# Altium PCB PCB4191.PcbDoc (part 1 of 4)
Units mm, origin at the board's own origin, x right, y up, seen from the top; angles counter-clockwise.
Board outline 160 x 160 mm, 6 copper layers (Top Layer, IM1 RIS, IM2 Signal, IM3 Signal, IM4 GND, Bottom Layer), stack 1.582 mm thick; 143 components, 121 nets, 430 pads, 4983 vias.
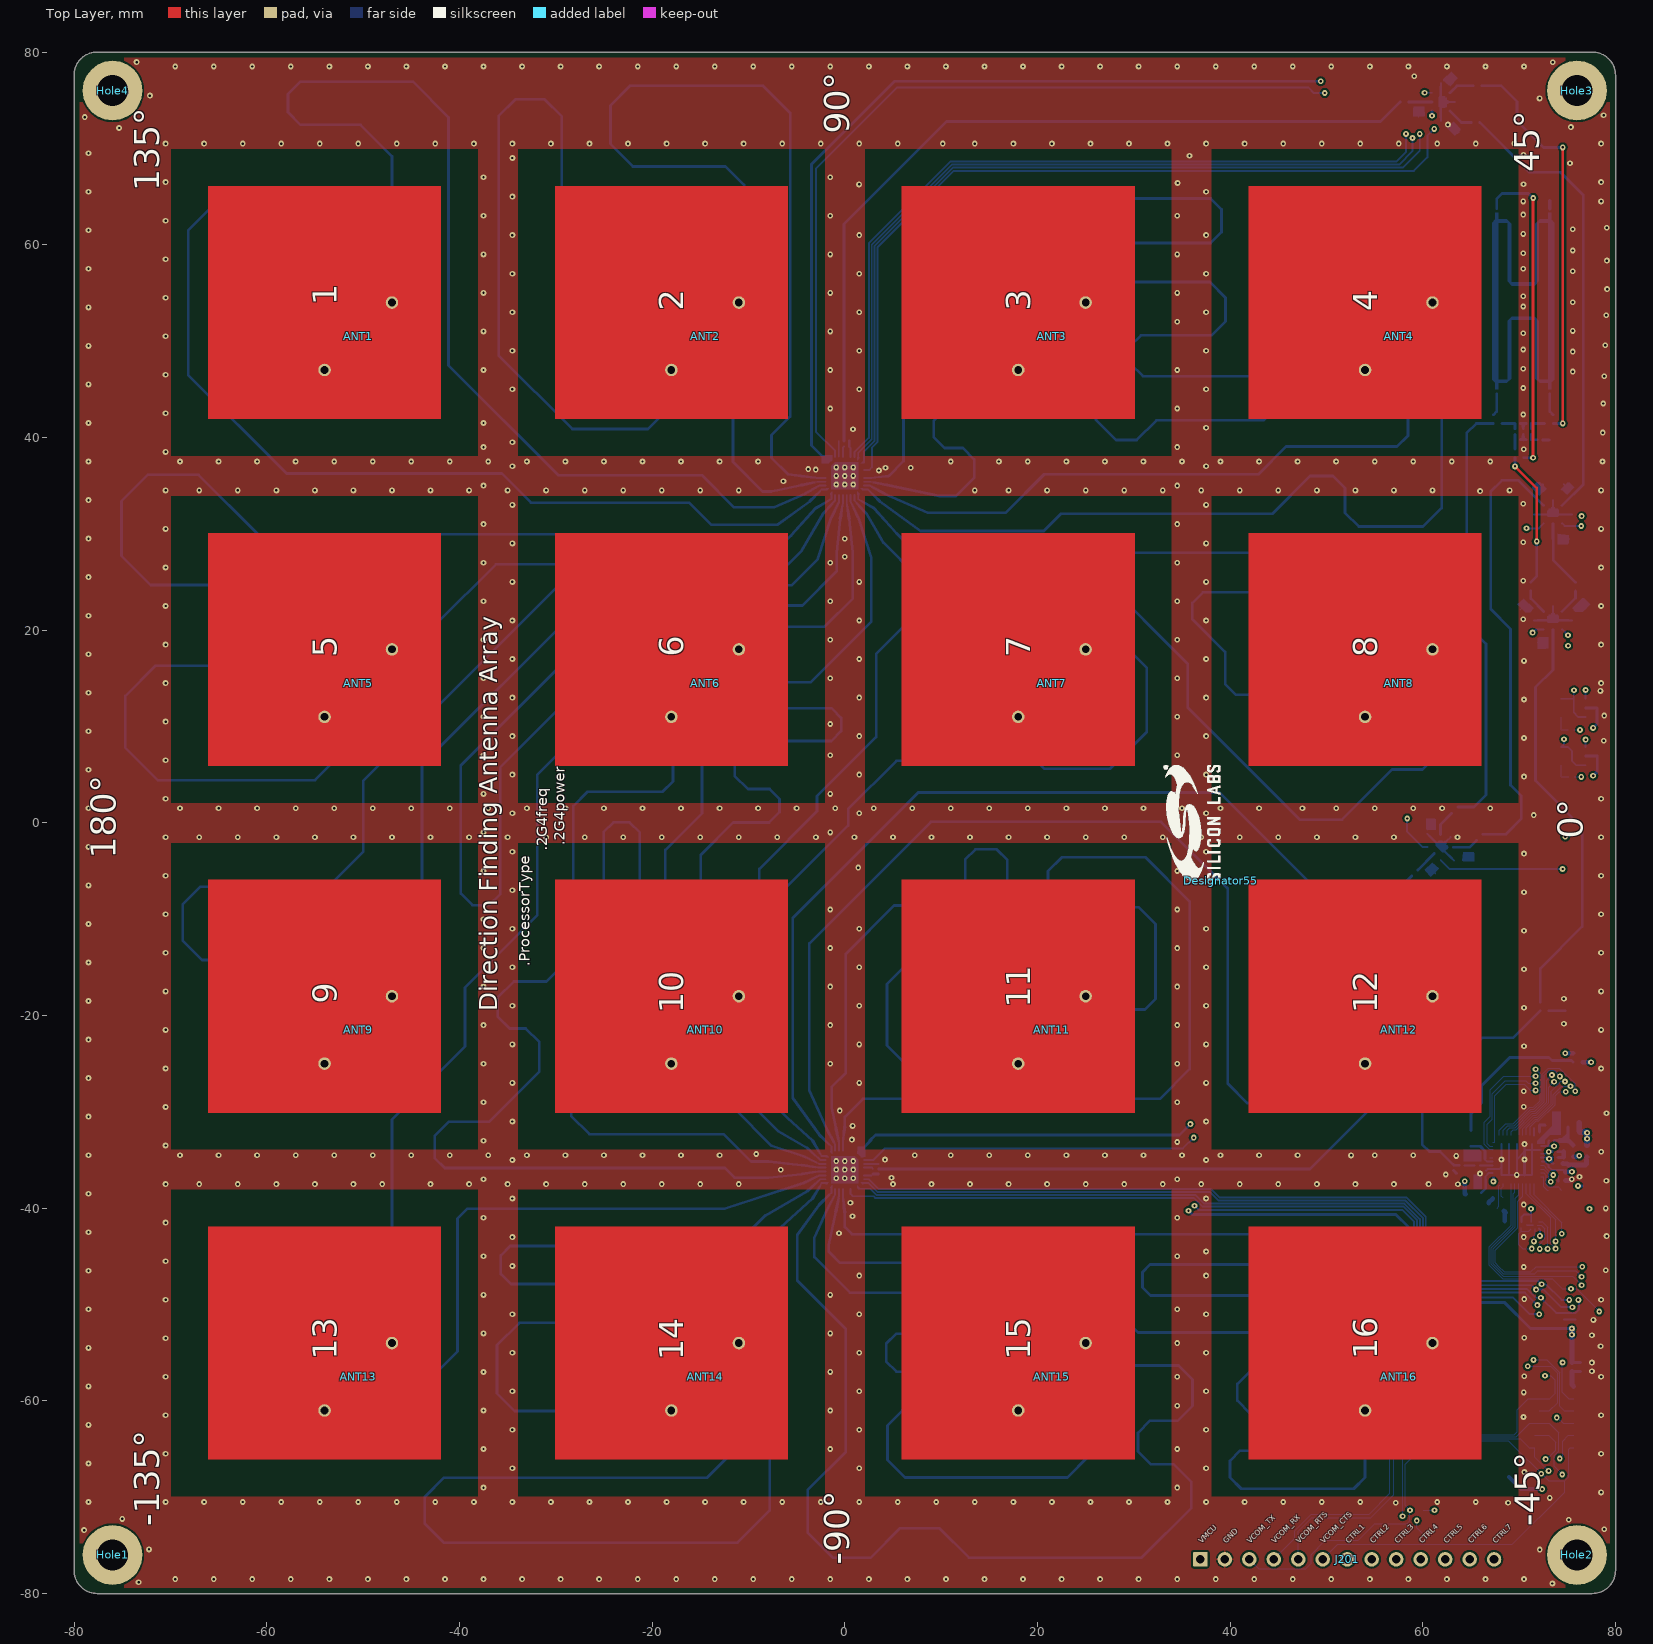
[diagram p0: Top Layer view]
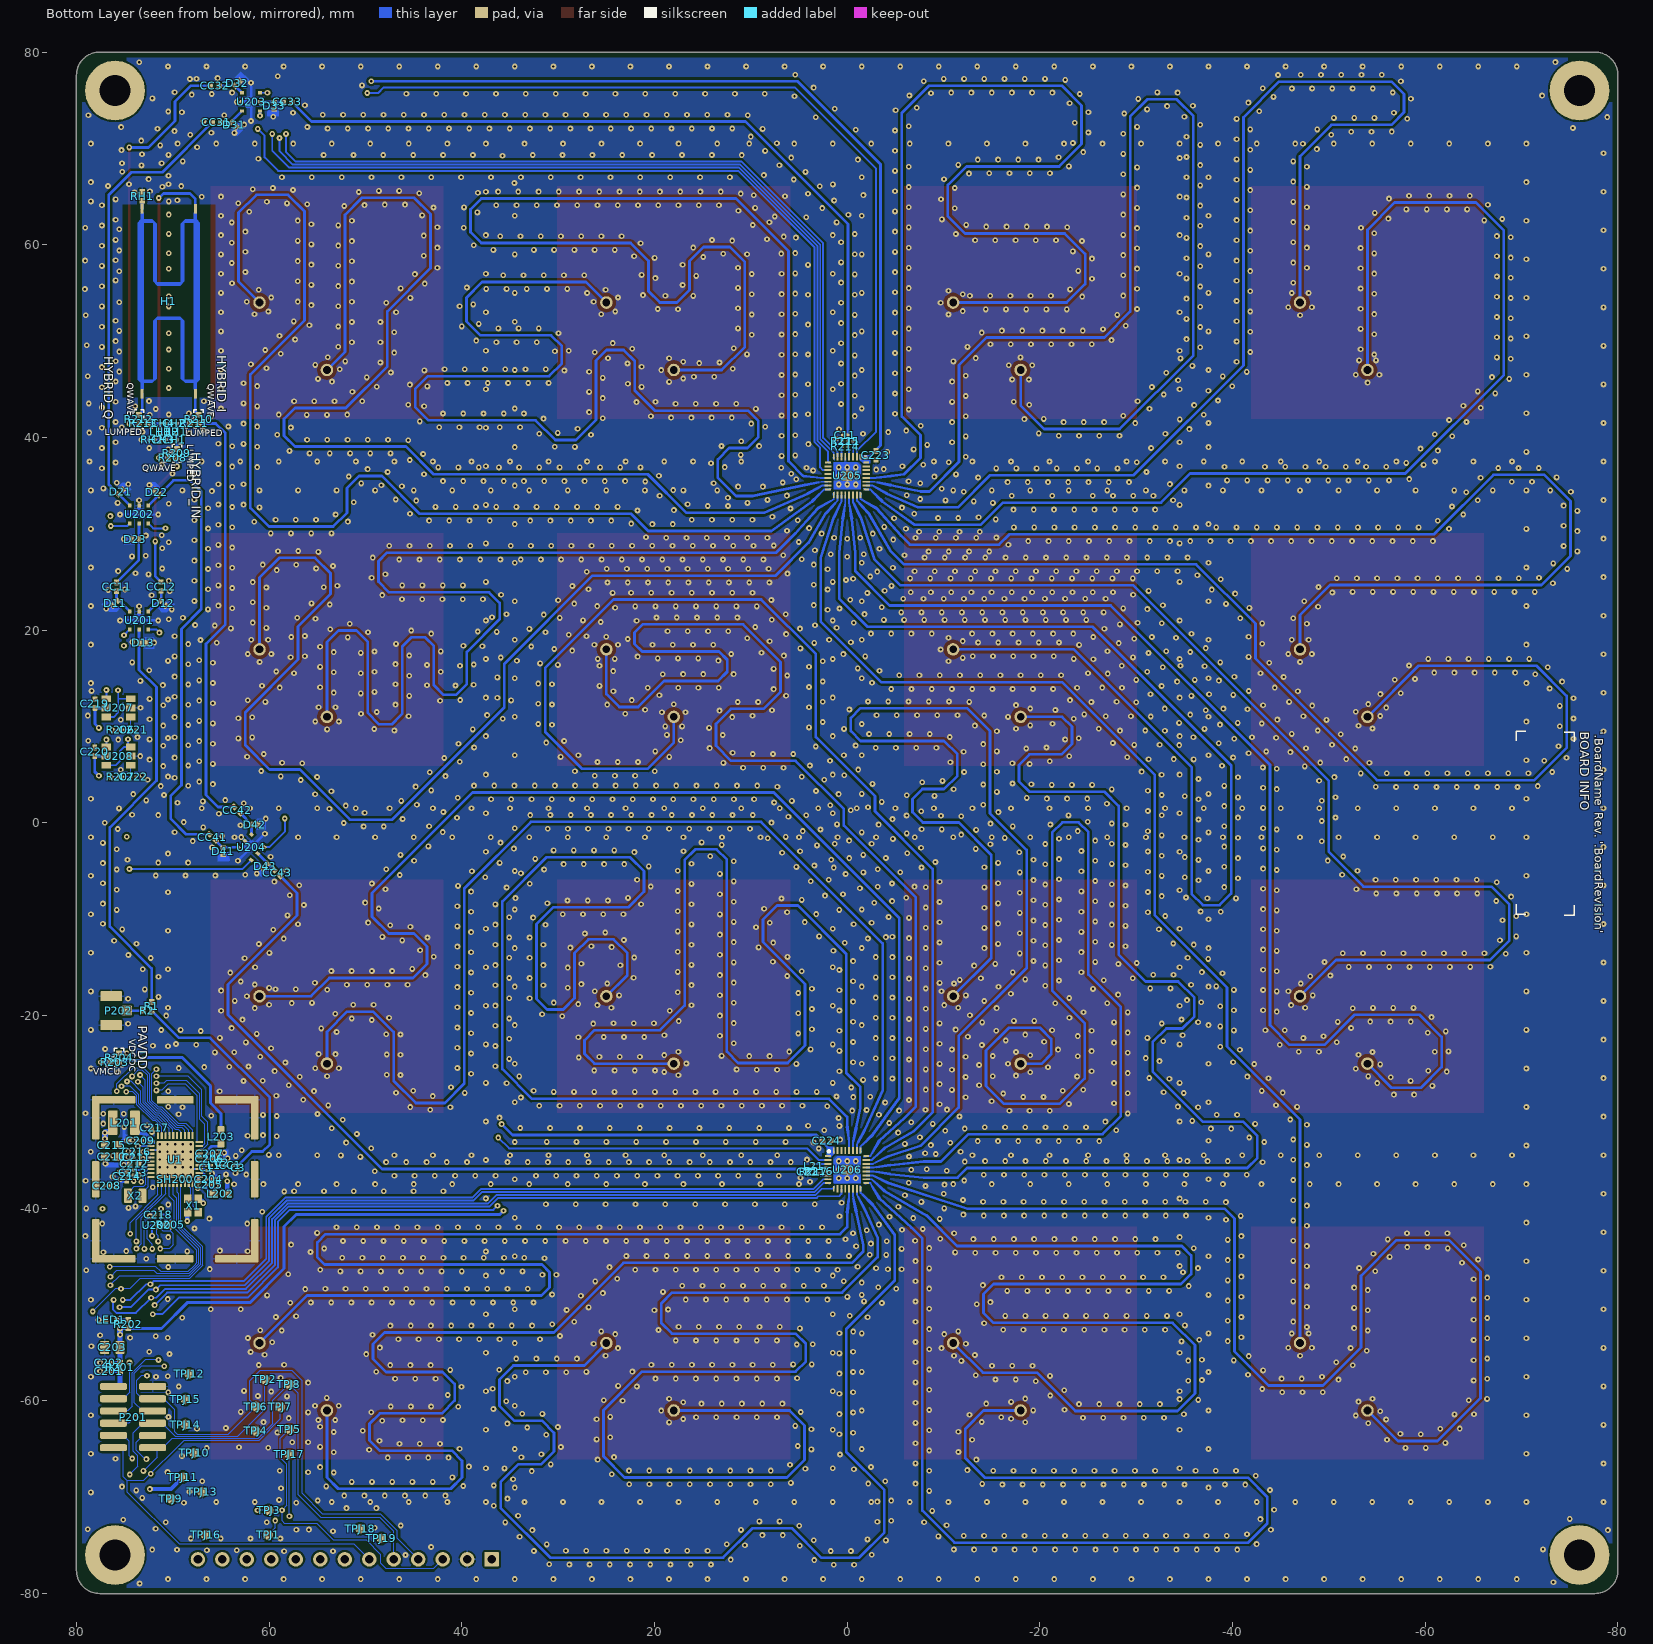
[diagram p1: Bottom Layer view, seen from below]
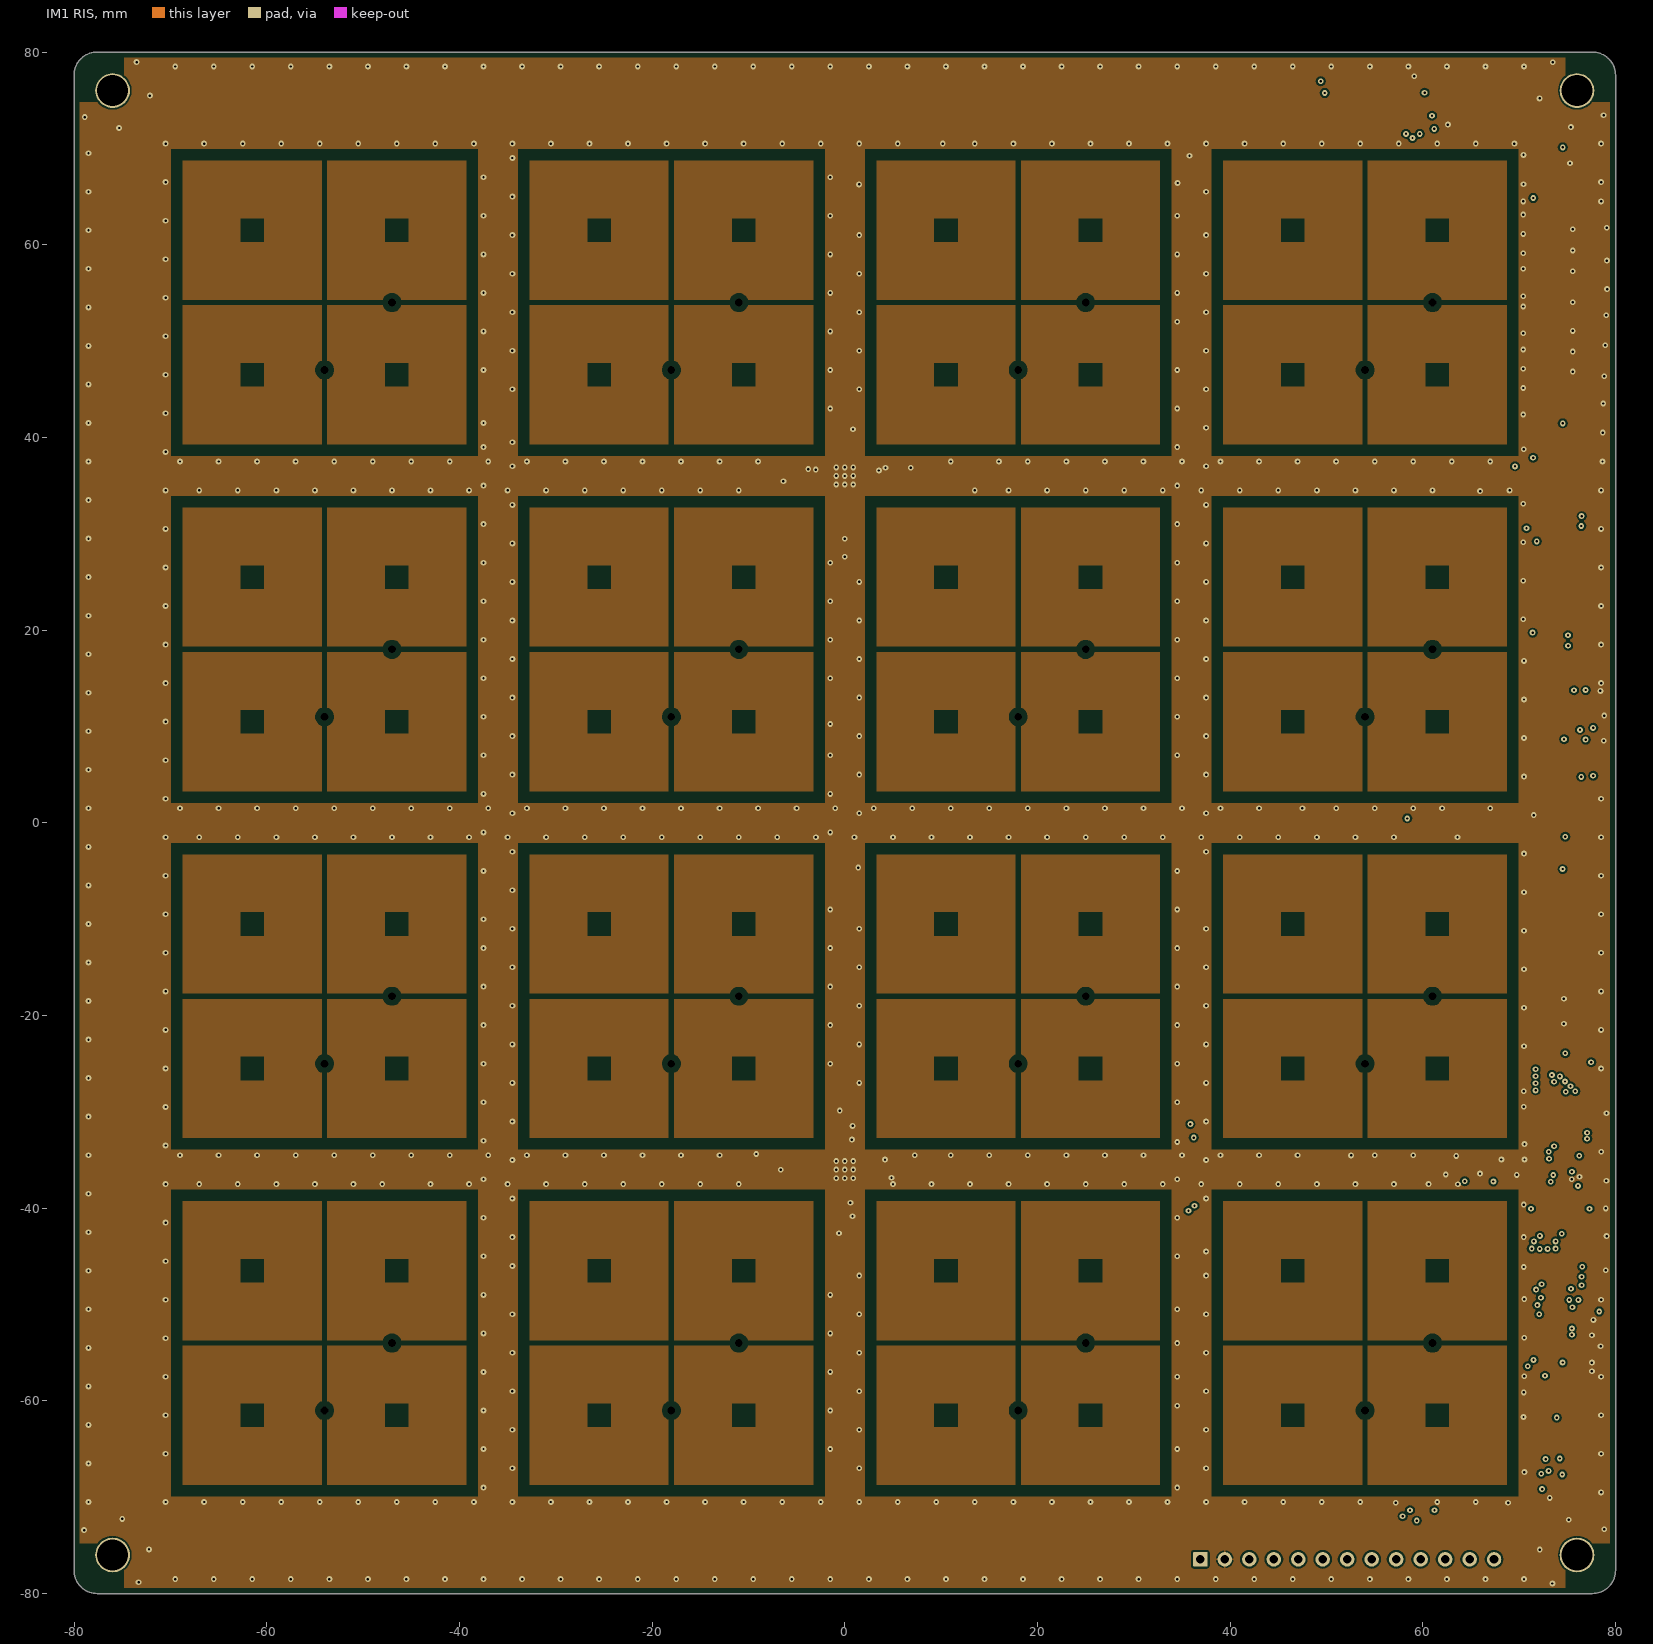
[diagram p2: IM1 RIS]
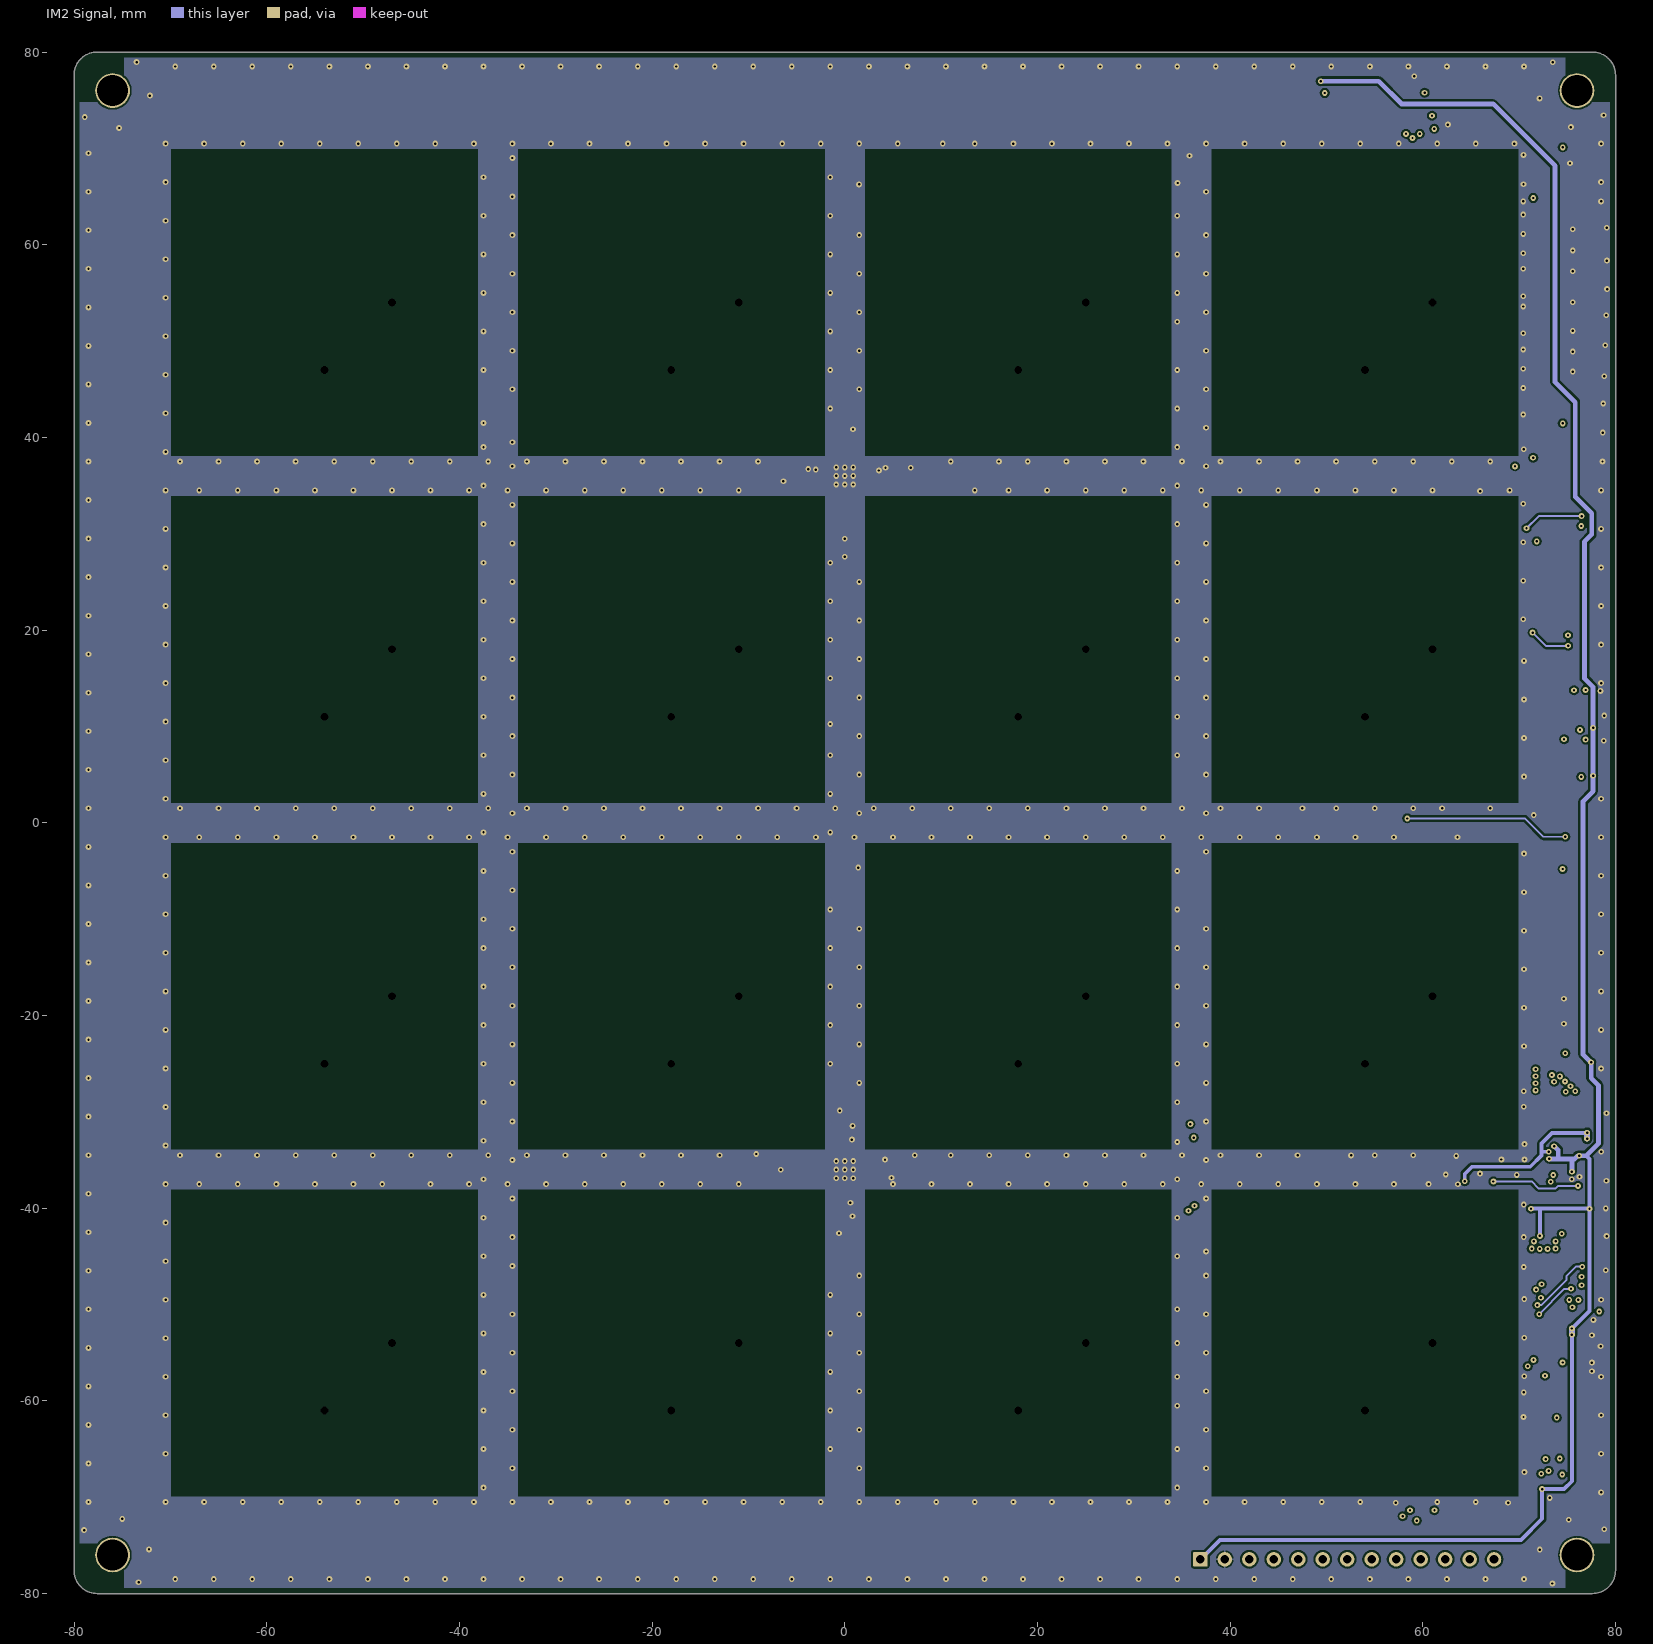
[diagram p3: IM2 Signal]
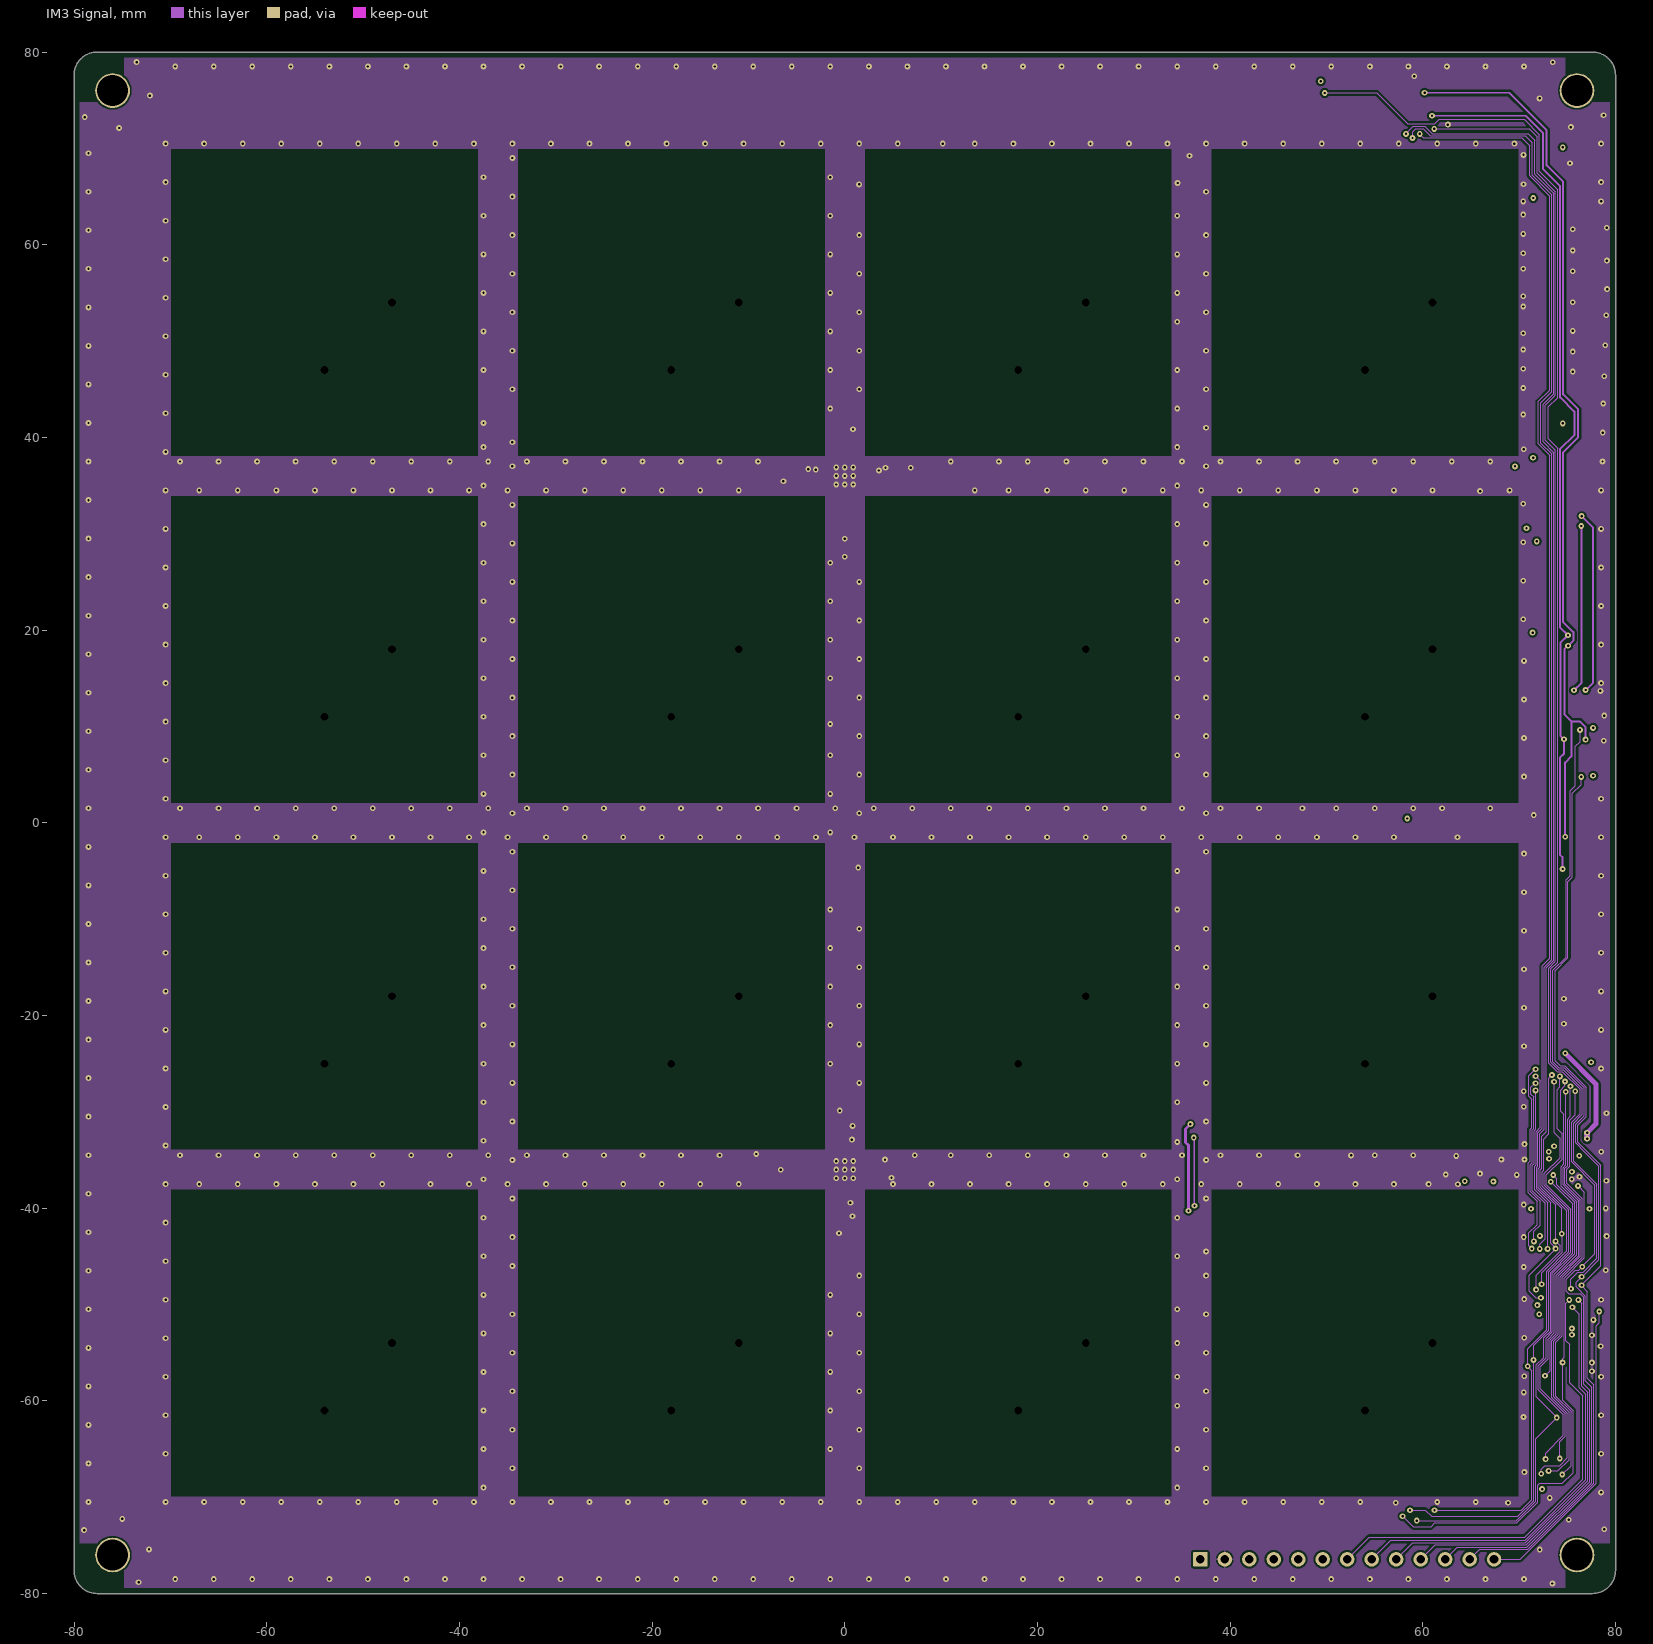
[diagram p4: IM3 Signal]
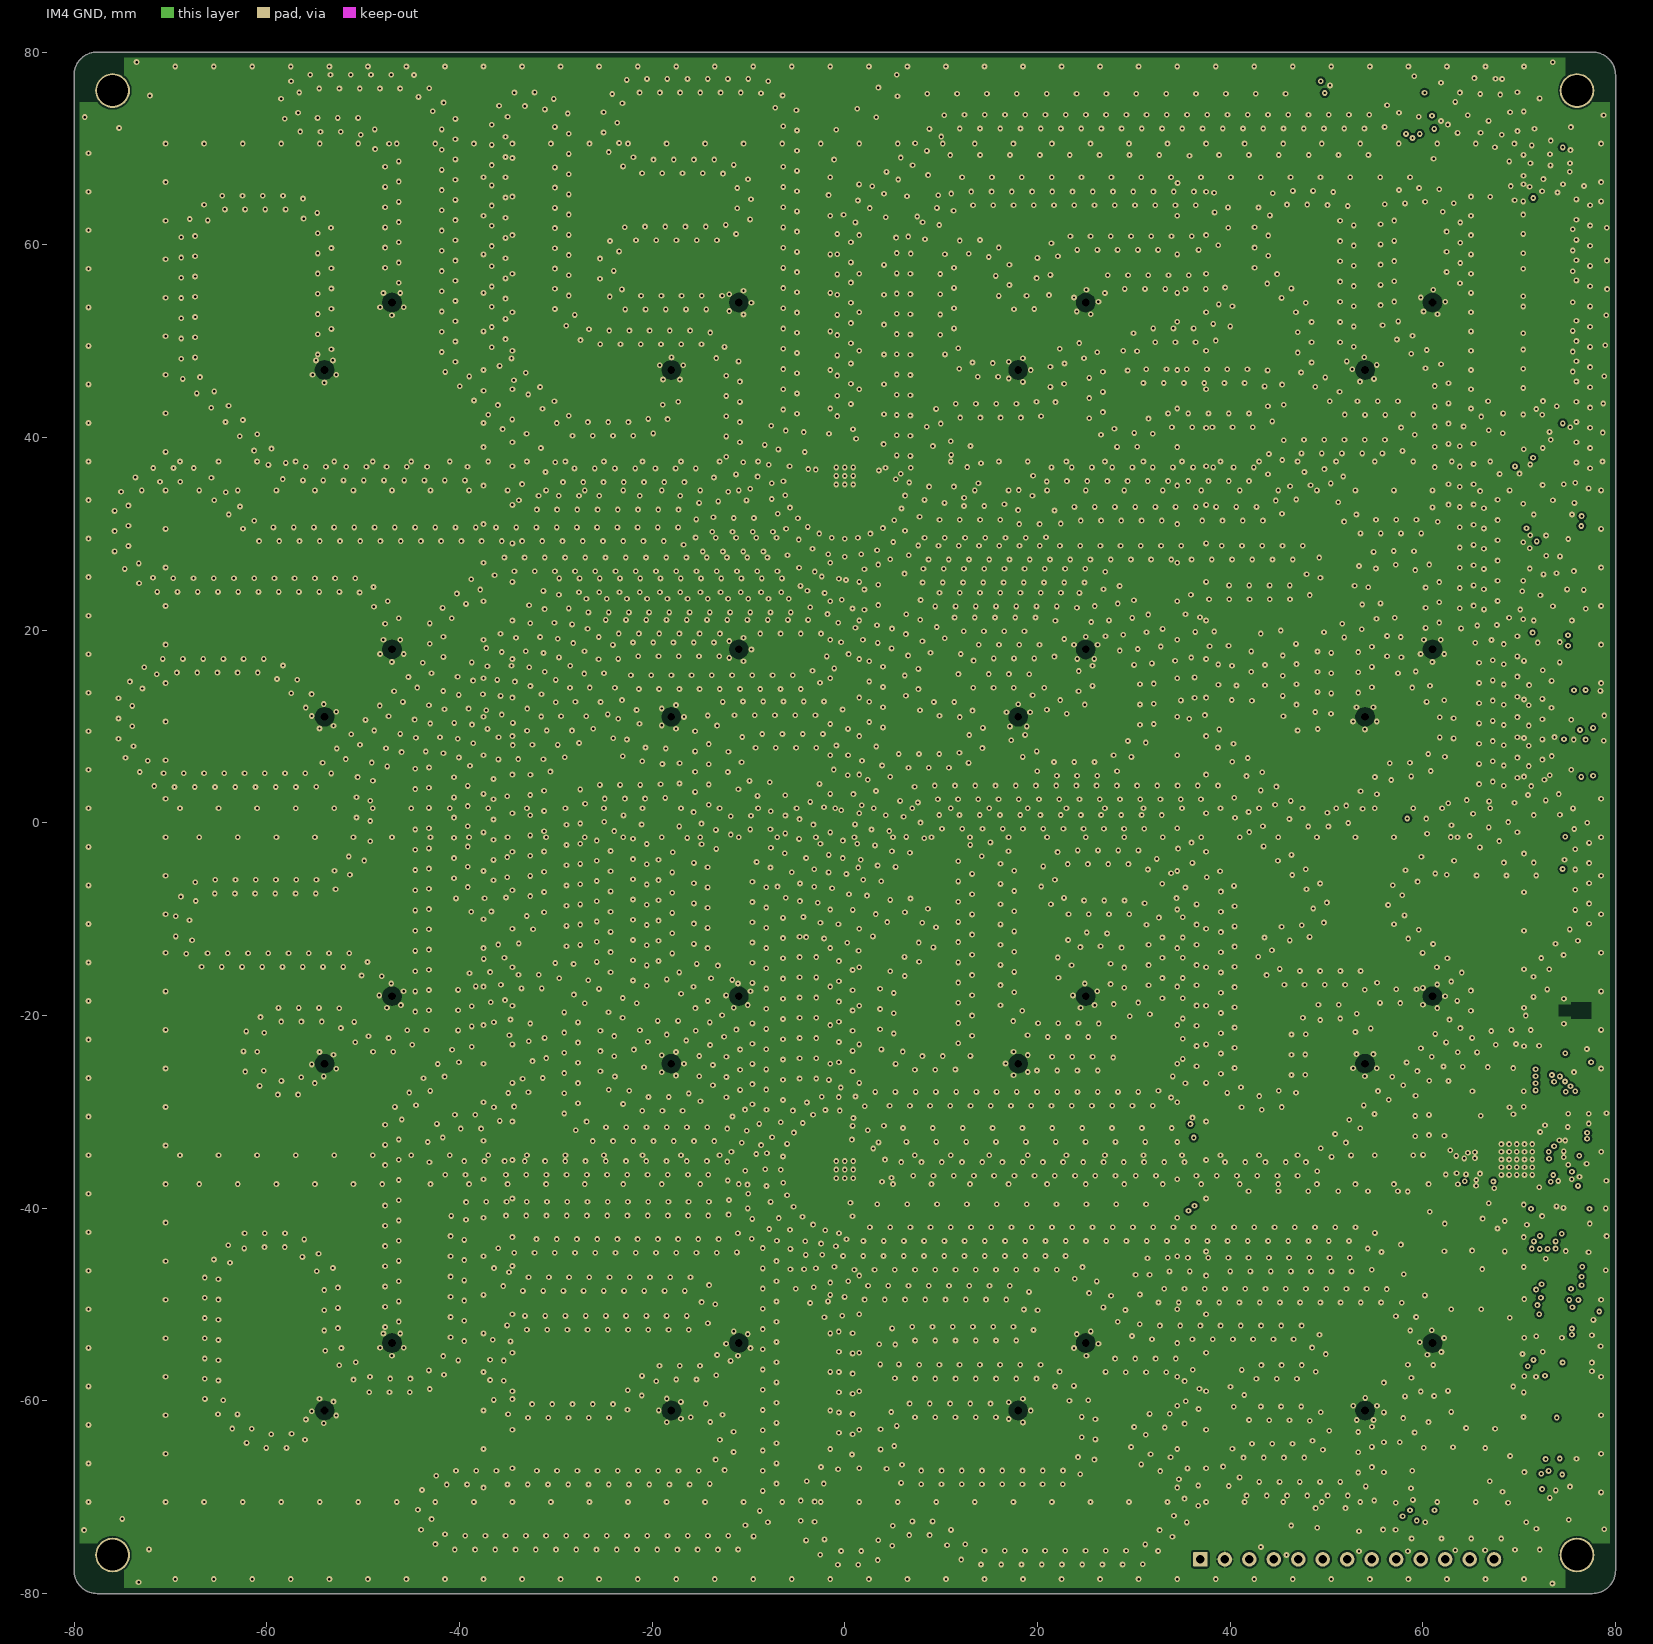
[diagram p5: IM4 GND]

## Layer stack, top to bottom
Top Solder: solder mask 0.0102, Solder Resist, Dk 3.5
Top Layer: signal copper 0.035
Dielectric 1: core 0.2, FR-4, Dk 4.4
IM1 RIS: signal copper 0.018
Dielectric 5: prepreg 0.42, Dk 4.2
IM2 Signal: signal copper 0.018
Dielectric 4: core 0.2, Dk 4.2
IM3 Signal: signal copper 0.018
Dielectric 3: prepreg 0.42, Dk 4.2
IM4 GND: signal copper 0.018
Dielectric 2: core 0.2, Dk 4.2
Bottom Layer: signal copper 0.035
Bottom Solder: solder mask 0.0102, Solder Resist, Dk 3.5

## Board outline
-80,-77.6 -80,77.6 cw(c-77.6,77.6) -77.6,80 77.6,80 cw(c77.6,77.6) 80,77.6 80,-77.6 cw(c77.6,-77.6) 77.6,-80 -77.6,-80 cw(c-77.6,-77.6)

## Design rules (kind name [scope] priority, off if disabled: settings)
AcuteAngle [All] p1: minimum=7.00000000000000E+0001 checktracksonly=FALSE
BoardOutlineClearance [All] p1: gap=0.6
Clearance Clearance_50Ohm [InNet('*ANT_*') vs InNet('GND')] p1: gap=0.2 except(0.23: Track-Poly)
Clearance Clearance_to_Holes [InPadClass('NPTH')] p2: gap=0.254
Clearance Clerance_Polygon [InPolygon] p3: gap=0.2 except(0.23: Track-Poly)
Clearance Clearance_General [All] p4: gap=0.1 except(0.23: Track-Poly)
HoleSize [All] p1: absolutevalues=TRUE maxlimit=5 minlimit=0.025 maxpercent=80.000 minpercent=20.000
HoleToHoleClearance HoleToHoleClearance_ANT1toPAD [Incomponent ('ANT1') vs ISpad] p1: gap=0 allowstackedmicrovias=TRUE
HoleToHoleClearance HoleToHoleClearance_R1toR2_1 [Incomponent ('R1') vs Incomponent ('R2')] p2: gap=0 allowstackedmicrovias=TRUE
HoleToHoleClearance HoleToHoleClearance_U1toVIA_1 [InComponent ('U1') vs IsVia] p3: gap=0 allowstackedmicrovias=TRUE
HoleToHoleClearance [All] p4: gap=0.254 allowstackedmicrovias=TRUE
MinimumSolderMaskSliver [All] p1: minsoldermaskwidth=0.102
PolygonConnect Polygon_VIA_Connect [IsVia] p1: connectstyle=Direct reliefconductorwidth=0.254 reliefentries=4 polygonreliefangle="90 Angle" airgapwidth=0.254
PolygonConnect PolygonConnect_SH100 [InComponent('SH100')] p2: connectstyle=Direct reliefconductorwidth=0.254 reliefentries=4 polygonreliefangle="90 Angle" airgapwidth=0.127
PolygonConnect [All] p3: connectstyle=Relief reliefconductorwidth=0.2 reliefentries=4 polygonreliefangle="90 Angle" airgapwidth=0.15
RoutingVias [All] p1: holewidth=0.3 width=0.65 viastyle="Through Hole" minholewidth=0.25 minwidth=0.5 maxholewidth=1 maxwidth=1.5
ShortCircuit ShortCircuit_Hybrid [InComponent('H1') and InNet('50R_HYBRID_*') vs InComponent('H1') or InNet('50R_HYBRID_*')] p1: allowed=TRUE
ShortCircuit ShortCircuit_Antenna [Incomponent ('ANT*') vs Incomponent ('ANT*')] p2: allowed=TRUE
ShortCircuit [All] p3: allowed=FALSE
SilkToSilkClearance [All] p1: silktosilkclearance=0.102
SilkToSolderMaskClearance [IsPad] p1: minsilkscreentomaskgap=0.102 clearancetoexposedcopper=TRUE
SolderMaskExpansion [All] p1: expansion=0.051
Width 50ohm [InNet('50R*')] p1: maxlimit=0.3 minlimit=0.1 preferedwidth=0.28
Width [All] p2: maxlimit=5.08 minlimit=0.1 preferedwidth=0.125
24 further rules are at their usual default settings.

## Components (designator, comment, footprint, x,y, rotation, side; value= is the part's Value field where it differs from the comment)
ANT1 "RECT_DP_PATCH_6LAYER_4x4_RIS" PATCH_RECT24mm2_14mm4RIS_31mm8CELL -54,54 r270 top
ANT2 "RECT_DP_PATCH_6LAYER_4x4_RIS" PATCH_RECT24mm2_14mm4RIS_31mm8CELL -18,54 r270 top
ANT3 "RECT_DP_PATCH_6LAYER_4x4_RIS" PATCH_RECT24mm2_14mm4RIS_31mm8CELL 18,54 r270 top
ANT4 "RECT_DP_PATCH_6LAYER_4x4_RIS" PATCH_RECT24mm2_14mm4RIS_31mm8CELL 54,54 r270 top
ANT5 "RECT_DP_PATCH_6LAYER_4x4_RIS" PATCH_RECT24mm2_14mm4RIS_31mm8CELL -54,18 r270 top
ANT6 "RECT_DP_PATCH_6LAYER_4x4_RIS" PATCH_RECT24mm2_14mm4RIS_31mm8CELL -18,18 r270 top
ANT7 "RECT_DP_PATCH_6LAYER_4x4_RIS" PATCH_RECT24mm2_14mm4RIS_31mm8CELL 18,18 r270 top
ANT8 "RECT_DP_PATCH_6LAYER_4x4_RIS" PATCH_RECT24mm2_14mm4RIS_31mm8CELL 54,18 r270 top
ANT9 "RECT_DP_PATCH_6LAYER_4x4_RIS" PATCH_RECT24mm2_14mm4RIS_31mm8CELL -54,-18 r270 top
ANT10 "RECT_DP_PATCH_6LAYER_4x4_RIS" PATCH_RECT24mm2_14mm4RIS_31mm8CELL -18,-18 r270 top
ANT11 "RECT_DP_PATCH_6LAYER_4x4_RIS" PATCH_RECT24mm2_14mm4RIS_31mm8CELL 18,-18 r270 top
ANT12 "RECT_DP_PATCH_6LAYER_4x4_RIS" PATCH_RECT24mm2_14mm4RIS_31mm8CELL 54,-18 r270 top
ANT13 "RECT_DP_PATCH_6LAYER_4x4_RIS" PATCH_RECT24mm2_14mm4RIS_31mm8CELL -54,-54 r270 top
ANT14 "RECT_DP_PATCH_6LAYER_4x4_RIS" PATCH_RECT24mm2_14mm4RIS_31mm8CELL -18,-54 r270 top
ANT15 "RECT_DP_PATCH_6LAYER_4x4_RIS" PATCH_RECT24mm2_14mm4RIS_31mm8CELL 18,-54 r270 top
ANT16 "RECT_DP_PATCH_6LAYER_4x4_RIS" PATCH_RECT24mm2_14mm4RIS_31mm8CELL 54,-54 r270 top
C1 "1P2" C0201_L 66.5,-35.825 r270 bottom
C2 "1P3" C0201_L 64.85,-35.281 r90 bottom
C3 "TBD" C0201_L 63.2,-35.825 r270 bottom
C11 "1P0" C0201_L 0.209,40.218 r180 bottom
C21 "1P0" C0201_L 4.111,-36.199 r90 bottom
C201 "100N" C0201_L 76.65,-56.937 r0 bottom
C202 "100N" C0201_L 76.65,-56.037 r0 bottom
C203 "10U" C0805_L 76.275,-54.462 r0 bottom
C204 "120P" C0201_L 66.25,-37 r180 bottom
C205 "100N" C0201_L 66.25,-37.55 r180 bottom
C206 "120P" C0201_L 66.175,-34.881 r180 bottom
C207 "100N" C0201_L 66.175,-34.331 r180 bottom
C208 "100N" C0201_L 76.852,-37.686 r0 bottom
C209 "100N" C0201_L 73.35,-32.981 r0 bottom
C210 "10U" C0603_L 76.35,-34.656 r0 bottom
C211 "10N" C0201_L 73.75,-34.725 r0 bottom
C212 "1U" C0402_L 74.025,-35.375 r0 bottom
C213 "100N" C0201_L 74.1,-36.306 r270 bottom
C214 "1U" C0402_L 74.775,-36.681 r270 bottom
C215 "4U7" C0603_L 76.35,-33.456 r180 bottom
C216 "100N" C0201_L 73.75,-34.15 r0 bottom
C217 "1U" C0201_L 71.85,-31.675 r0 bottom
C218 "100N" C0201_L 71.525,-40.675 r0 bottom
C219 "100N" C0402_L 78.078,12.371 r270 bottom
C220 "100N" C0402_L 78.097,7.378 r270 bottom
C221 "TBD" C0201_L 74.08,9.639 r0 bottom
C222 "TBD" C0201_L 74.079,4.759 r0 bottom
C223 "100N" C0402_L -2.987,38.141 r90 bottom
C224 "100N" C0402_L 2.113,-33.009 r0 bottom
CC1 "18P" C0201_L 64.025,-35.55 r180 bottom
CC11 "12P" C0402_L 75.838,24.504 r270 bottom
CC12 "12P" C0402_L 71.212,24.524 r270 bottom
CC31 "12P" C0402_L 65.47,72.692 r0 bottom
CC32 "12P" C0402_L 65.656,76.507 r0 bottom
CC33 "12P" C0402_L 58.101,74.825 r0 bottom
CC41 "12P" C0402_L 65.886,-1.507 r45 bottom
CC42 "12P" C0402_L 63.32,1.322 r45 bottom
CC43 "12P" C0402_L 59.168,-5.21 r45 bottom
CH1 "1P1" C0201_L 69.842,39.753 r0 bottom
CH2 "1P1" C0201_L 69.842,41.453 r0 bottom
CH3 "1P1" C0201_L 70.992,39.753 r0 bottom
CH4 "1P1" C0201_L 70.992,41.453 r0 bottom
D11 "ESD7551" X2DFN2_1.0x0.6_0.65P 76,22.8 r135 bottom
D12 "ESD7551" X2DFN2_1.0x0.6_0.65P 71,22.8 r45 bottom
D13 "ESD7551" X2DFN2_1.0x0.6_0.65P 73.075,18.675 r0 bottom
D21 "ESD7551" X2DFN2_1.0x0.6_0.65P 75.424,34.355 r315 bottom
D22 "ESD7551" X2DFN2_1.0x0.6_0.65P 71.648,34.284 r225 bottom
D23 "ESD7551" X2DFN2_1.0x0.6_0.65P 73.889,29.455 r180 bottom
D31 "ESD7551" X2DFN2_1.0x0.6_0.65P 63.648,72.456 r45 bottom
D32 "ESD7551" X2DFN2_1.0x0.6_0.65P 63.291,76.738 r315 bottom
D33 "ESD7551" X2DFN2_1.0x0.6_0.65P 59.476,74.436 r90 bottom
D41 "ESD7551" X2DFN2_1.0x0.6_0.65P 64.765,-2.963 r90 bottom
D42 "ESD7551" X2DFN2_1.0x0.6_0.65P 61.485,-0.188 r0 bottom
D43 "ESD7551" X2DFN2_1.0x0.6_0.65P 60.415,-4.513 r135 bottom
Designator55 "Comment" LOGO_SILABS_W12.0 39,-6 r90 top
Designator167 "Comment" PCB_SPEC_6_LAYER_BLINDVIA -91,310 r0 top
H1 "90DEG_HYBRID_6LAYER" 90DEG_HYBRID_EUROCIRCUITS_6LAYER_0mm2 70.42,54.146 r270 bottom
Hole1 "Comment" 3MM_PLATED -76,-76 r0 top
Hole2 "Comment" 3MM_PLATED 76,-76 r0 top
Hole3 "Comment" 3MM_PLATED 76,76 r0 top
Hole4 "Comment" 3MM_PLATED -76,76 r0 top
J201 "1X13 2.54MM" HEADER_1X13_2.54MM_TH 52.15,-76.45 r0 top
L1 "2N6" COIL_0201_L 65.675,-35.55 r180 bottom
L11 "2N" R0201_L#1 -0.337,39.625 r180 bottom
L21 "2N" R0201_L#1 3.497,-35.656 r90 bottom
L201 "2U2" COIL_1008_L 75.082,-31.125 r0 bottom
L202 "BLM18AG102SN1" COIL_MUR_BLM18_0603 65.05,-38.525 r0 bottom
L203 "BLM18AG102SN1" COIL_MUR_BLM18_0603 65,-32.6 r270 bottom
LED1 "GREEN" LED0402_L 76.375,-51.575 r180 bottom
LH1 "3N3" COIL_0201_L 69.567,40.603 r90 bottom
LH2 "3N3" COIL_0201_L 70.417,40.603 r90 bottom
LH3 "3N3" COIL_0201_L 71.267,40.603 r90 bottom
P201 "HEADER_2X6_1.27MM_SMD" FTSH_106_01_L_DV_K 74.125,-61.687 r270 bottom
P202 "U.FL" COAX_HIROSE_U.FL_CL331-0471 76.395,-19.497 r270 bottom
R1 "0R" R0402_L 72.195,-19.047 r90 bottom
R2 "0R" R0402_L 72.645,-19.497 r0 bottom
R201 "0R" R0402_L 75.475,-56.487 r90 bottom
R202 "1K96" R0402_L 74.625,-52.025 r90 bottom
R203 "0R" R0402_L 76.021,-24.833 r0 bottom
R204 "0R" R0402_L 75.575,-24.375 r270 bottom
R205 "330K" R0201_L#2 70.225,-41.725 r90 bottom
R206 "0R" R0201_L#1 75.38,9.639 r180 bottom
R207 "0R" R0201_L#1 75.419,4.76 r180 bottom
R208 "0R" R0402_L 70.017,37.889 r0 bottom
R209 "0R" R0402_L 69.567,38.339 r270 bottom
R210 "0R" R0402_L 67.32,41.9 r270 bottom
R211 "0R" R0402_L 67.77,41.45 r180 bottom
R212 "0R" R0402_L 73.52,41.9 r270 bottom
R213 "0R" R0402_L 73.07,41.45 r0 bottom
R214 "0R" R0201_L#1 0.188,39.05 r180 bottom
R215 "0R" R0201_L#1 0.213,39.625 r0 bottom
R216 "0R" R0201_L#1 2.922,-36.181 r90 bottom
R217 "0R" R0201_L#1 3.497,-36.206 r270 bottom
RH1 "50R" R0402_L 73.175,65.025 r90 bottom
RH2 "50R" R0201_L#1 72.142,39.753 r0 bottom
SH200 "RF_SHIELD_FRAME_BMI-S-202-F" LAIRD_BMI-S-202-F 69.75,-37 r180 bottom locked
TPJ1 "TPJ_SMD" TP_1.0_SMD 60.098,-73.907 r90 bottom locked
TPJ2 "TPJ_SMD" TP_1.0_SMD 60.449,-57.777 r90 bottom locked
TPJ3 "TPJ_SMD" TP_1.0_SMD 60.049,-71.357 r90 bottom locked
TPJ4 "TPJ_SMD" TP_1.0_SMD 61.399,-63.107 r90 bottom locked
TPJ5 "TPJ_SMD" TP_1.0_SMD 57.899,-62.957 r90 bottom locked
TPJ6 "TPJ_SMD" TP_1.0_SMD 61.369,-60.587 r90 bottom locked
TPJ7 "TPJ_SMD" TP_1.0_SMD 58.839,-60.627 r90 bottom locked
TPJ8 "TPJ_SMD" TP_1.0_SMD 57.949,-58.257 r90 bottom locked
TPJ9 "TPJ_SMD" TP_1.0_SMD 70.199,-70.157 r90 bottom locked
TPJ10 "TPJ_SMD" TP_1.0_SMD 67.799,-65.407 r90 bottom locked
TPJ11 "TPJ_SMD" TP_1.0_SMD 68.949,-67.907 r90 bottom locked
TPJ12 "TPJ_SMD" TP_1.0_SMD 68.299,-57.207 r90 bottom locked
TPJ13 "TPJ_SMD" TP_1.0_SMD 66.949,-69.457 r90 bottom locked
TPJ14 "TPJ_SMD" TP_1.0_SMD 68.699,-62.457 r90 bottom locked
TPJ15 "TPJ_SMD" TP_1.0_SMD 68.699,-59.857 r90 bottom locked
TPJ16 "TPJ_SMD" TP_1.0_SMD 66.599,-73.907 r90 bottom locked
TPJ17 "TPJ_SMD" TP_1.0_SMD 57.899,-65.557 r90 bottom locked
TPJ18 "TPJ_SMD" TP_1.0_SMD 50.55,-73.287 r90 bottom locked
TPJ19 "TPJ_SMD" TP_1.0_SMD 48.349,-74.282 r90 bottom locked
U1 "EFR32BG22C224F512IM40" QFN40_M040_5.0X5.0_EP_SL 69.75,-34.95 r90 bottom
U200 "MX25R8035F" BGA8_M040_1.24X1.75_WLCSP 71.65,-41.775 r270 bottom
U201 "SKY13377-313LF" SKY13377-313LF 73.5,21 r270 bottom
U202 "SKY13377-313LF" SKY13377-313LF 73.5,32 r270 bottom
U203 "SKY13377-313LF" SKY13377-313LF 61.88,74.825 r180 bottom
U204 "SKY13377-313LF" SKY13377-313LF 61.84,-2.538 r225 bottom
U205 "CHW-SP16TS-B" QFN32_4X4MM_CHW-SP16TS-B 0,36 r270 bottom
U206 "CHW-SP16TS-B" QFN32_4X4MM_CHW-SP16TS-B 0,-36 r180 bottom
U207 "SN74LVC2G14" SOT-23-6_SN74LVC2G14 75.625,11.925 r0 bottom
U208 "SN74LVC2G14" SOT-23-6_SN74LVC2G14 75.625,6.925 r0 bottom
X1 "38.4 MHz" KDS_DSX211SH_2016 67.9,-39.725 r90 bottom
X2 "32.768 kHz" X_MCS_CM8V-T1A 73.9,-38.706 r0 bottom

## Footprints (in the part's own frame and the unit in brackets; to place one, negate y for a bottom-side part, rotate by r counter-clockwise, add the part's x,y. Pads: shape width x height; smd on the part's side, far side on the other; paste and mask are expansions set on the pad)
3MM_PLATED [mm] "3MM_PLATED"
  round 6.2 / inner round 3.6 / far side round 6.2 hole 3.2: 1(0,0)
90DEG_HYBRID_EUROCIRCUITS_6LAYER_0mm2 [mm]
  rect 1x0.33 smd paste-1: 1(-9.6,2.765) 2(-9.6,-2.765) 3(9.6,-2.765) 4(9.6,2.765)
  Top Layer pour cut-out: -10,4.8 -10,-4.8 10,-4.8 10,4.8
  Top Layer region: -9.15,-2.93 -8.48,-2.93 -8.15,-3.2 8.15,-3.2 8.48,-2.93 9.15,-2.93 9.15,-2.6 8.48,-2.6 8.48,-1.7 8.05,-1.27 1.95,-1.27 1.95,1.27 8.05,1.27 8.48,1.7 8.48,2.6 8.15,2.6 8.15,1.6 2.05,1.6 1.62,1.17 1.62,-1.17 2.05,-1.6 8.15,-1.6 8.15,-2.6 -8.15,-2.6 -8.15,-1.6 -2.05,-1.6 -1.62,-1.17 -1.62,1.17 -2.05,1.6 -8.15,1.6 -8.15,2.6 9.15,2.6 9.15,2.93 8.48,2.93 8.15,3.2 -8.15,3.2 -8.48,2.93 -9.15,2.93 -9.15,2.6 -8.48,2.6 -8.48,1.7 -8.05,1.27 -1.95,1.27 -1.95,-1.27 -8.05,-1.27 -8.48,-1.7 -8.48,-2.6 -9.15,-2.6
BGA8_M040_1.24X1.75_WLCSP [mm] "BGA, 8 pin. U100"
  round 0.21 smd mask+0.038: A1(-0.35,0.4) A3(0.35,0.4) B2(0,0.2) C1(-0.35,0) C3(0.35,0) D2(0,-0.2) E1(-0.35,-0.4) E3(0.35,-0.4)
  body extent -0.63,-0.89 0.63,0.88, height 0.52
C0201_L [mm] "Capacitor, Chip; 0.60 mm L X 0.30 mm W X 0.33 mm H body"
  rrect52% 0.31x0.34 smd: 1(-0.275,0) 2(0.275,0)
  body extent -0.3,-0.15 0.3,0.15, height 0.3
C0402_L [mm] "Chip Capacitor, 2-Leads, Body 1.0x0.5mm, IPC High Density"
  rrect20% 0.6x0.5 smd mask+0.051: 1(-0.45,0) 2(0.45,0)
  body extent -0.5,-0.25 0.5,0.25, height 0.6
C0603_L [mm] "Capacitor, 0603, High Density (C)"
  rrect25% 0.8x0.85 smd: 1(-0.7,0) 2(0.7,0)
  body extent -0.8,-0.4 0.8,0.4, height 0.95
C0805_L [mm] "Capacitor, 0805"
  rrect25% 0.95x1.35 smd: 1(-0.8,0) 2(0.8,0)
  body extent -1.1,-0.72 1.1,0.72, height 1.45
COAX_HIROSE_U.FL_CL331-0471 [mm] "COAX_HIROSE_U.FL_CL331-0471"
  rrect20% 1.05x1.1 smd mask+0.051: 1(0,1.6)
  rrect20% 1.05x2.25 smd mask+0.051: 2(-1.5,0) 3(1.5,0)
  Top Layer pour cut-out: -0.85,0.9 0.85,0.9 0.85,0.9 0.85,-1.2 -0.85,-1.2 -0.85,-1.2
  body extent -1.3,-1.55 1.3,1.3, height 0.9
COIL_0201_L [mm] "JELF243C-0021"
  rrect10% 0.3x0.3 smd: 1(-0.3,0) 2(0.3,0)
  body extent -0.32,-0.17 0.32,0.17, height 0.33
COIL_1008_L [mil] "Chip Inductors, 1008 (2520), Coilcraft (190207)"
  rrect25% 40x100 smd: 1(-45,0) 2(45,0)
  body extent -58,-55 58,55, height 80
COIL_MUR_BLM18_0603 [mm] "COIL_MUR_BLM18P_0603"
  rrect25% 0.85x0.7 smd mask+0.051: 1(-0.7,0) 2(0.7,0)
  body extent -0.88,-0.48 0.87,0.48, height 0.95
FTSH_106_01_L_DV_K [mil] "FTSH-105-01-L-DV-K-P-TR"
  rrect50% 29x110 smd: 1(-125,-80) 2(-125,80) 3(-75,-80) 4(-75,80) 5(-25,-80) 6(-25,80) 7(25,-80) 8(25,80) 9(75,-80) 10(75,80) 11(125,-80) 12(125,80)
  body extent -150,-115 150,115, height 231
HEADER_1X13_2.54MM_TH [mm] "Connector; Header; 2 Position"
  rrect10% 1.5x1.5 hole 0.9: 1(-15.242,0)
  round 1.5 hole 0.9: 2(-12.702,0) 3(-10.162,0) 4(-7.622,0) 5(-5.082,0) 6(-2.542,0) 7(-0.002,0) 8(2.542,0) 9(5.082,0) 10(7.622,0) 11(10.162,0) 12(12.702,0) 13(15.242,0)
  body extent -16.51,-1.27 16.51,1.27, height 9.7
KDS_DSX211SH_2016 [mm] "Copy of Silabs CE  X_KDS_DSX211SH_2.0X1.65-4"
  rrect20% 0.9x0.8 smd mask+0.051: 1(-0.7,-0.55) 2(0.7,-0.55) 3(0.7,0.55) 4(-0.7,0.55)
  body extent -1.07,-0.87 1.08,0.88, height 0.5
LAIRD_BMI-S-202-F [mm] "laired BMI-S-202-F"
  rrect20% 0.75x4.5 smd paste+0 mask+0.05: 1(-8.25,-6.375) 1(-8.25,6.375) 1(8.25,-6.375) 1(8.25,6.375)
  rrect20% 0.75x3.8 smd paste+0 mask+0.05: 1(-8.25,0) 1(8.25,0)
  rrect20% 4.5x0.75 smd paste+0 mask+0.05: 1(-6.375,8.25) 1(-6.375,-8.25) 1(6.375,8.25) 1(6.375,-8.25)
  rrect20% 3.8x0.75 smd paste+0 mask+0.05: 1(0,-8.25) 1(0,8.25)
  body extent -8.6,-8.6 8.6,8.6, height 5.5
LED0402_L [mm] "Led smd 0402"
  rrect25% 0.5x0.5 smd: 1(-0.525,0) 2(0.525,0)
  body extent -0.5,-0.25 0.5,0.25, height 0.3
LOGO_SILABS_W12.0 [mm] "LOGO_SILABS_W12.0 (170217)"
  silkscreen extent 0.03,0.03 11.99,5.88
PATCH_RECT24mm2_14mm4RIS_31mm8CELL [mm]
  round 1.3 / inner round 0 / far side round 1.3 hole 0.8 paste+0 mask+0: 1(7,0) 2(0,7)
  Top Layer region: -12.1,-12.1 12.1,-12.1 12.1,12.1 -12.1,12.1
  Top Layer pour cut-out: -15.9,-15.9 15.9,-15.9 15.9,15.9 -15.9,15.9
  IM3 Signal pour cut-out: -15.9,-15.9 15.9,-15.9 15.9,15.9 -15.9,15.9
  IM1 RIS pour cut-out: -0.3,-15.9 -0.3,15.9 0.3,15.9 0.3,-15.9
  IM1 RIS pour cut-out: -15.9,0.3 15.9,0.3 15.9,-0.3 -15.9,-0.3
  IM1 RIS pour cut-out: -15.9,-15.9 -15.9,15.9 -14.7,15.9 -14.7,-15.9
  IM1 RIS pour cut-out: 15.9,-15.9 -15.9,-15.9 -15.9,-14.7 15.9,-14.7
  IM1 RIS pour cut-out: 15.9,15.9 15.9,-15.9 14.7,-15.9 14.7,15.9
  IM1 RIS pour cut-out: -15.9,15.9 15.9,15.9 15.9,14.7 -15.9,14.7
  IM1 RIS pour cut-out: -8.7,8.7 -8.7,6.3 -6.3,6.3 -6.3,8.7
  IM1 RIS pour cut-out: 6.3,8.7 6.3,6.3 8.7,6.3 8.7,8.7
  IM1 RIS pour cut-out: 6.3,-6.3 6.3,-8.7 8.7,-8.7 8.7,-6.3
  IM1 RIS pour cut-out: -8.7,-6.3 -8.7,-8.7 -6.3,-8.7 -6.3,-6.3
  IM2 Signal pour cut-out: -15.9,-15.9 15.9,-15.9 15.9,15.9 -15.9,15.9
  Multi-Layer pour cut-out: 0,6 -0.383,6.076 -0.707,6.293 -0.924,6.617 -1,7 -1,7 -0.924,7.383 -0.707,7.707 -0.383,7.924 0,8 0,8 0.383,7.924 0.707,7.707 0.924,7.383 1,7 1,7 0.924,6.617 0.707,6.293 0.383,6.076 0,6
  Multi-Layer pour cut-out: 7,-1 6.617,-0.924 6.293,-0.707 6.076,-0.383 6,0 6,0 6.076,0.383 6.293,0.707 6.617,0.924 7,1 7,1 7.383,0.924 7.707,0.707 7.924,0.383 8,0 8,0 7.924,-0.383 7.707,-0.707 7.383,-0.924 7,-1
PCB_SPEC_6_LAYER_BLINDVIA [mm] "Patchantenna_version"
QFN32_4X4MM_CHW-SP16TS-B [mm]
  rect 1x1 smd: 0(0,0)
  rect 0.59x0.2 smd: 1(-1.985,1.4) 8(-1.985,-1.4) 17(1.985,-1.4) 24(1.985,1.4)
  rect 0.76x0.2 smd: 2(-1.985,1) 3(-1.985,0.6) 4(-1.985,0.2) 5(-1.985,-0.2) 6(-1.985,-0.6) 7(-1.985,-1) 18(1.985,-1) 19(1.985,-0.6) 20(1.985,-0.2) 21(1.985,0.2) 22(1.985,0.6) 23(1.985,1)
  rect 0.2x0.59 smd: 9(-1.4,-1.985) 16(1.4,-1.985) 25(1.4,1.985) 32(-1.4,1.985)
  rect 0.2x0.76 smd: 10(-1,-1.985) 11(-0.6,-1.985) 12(-0.2,-1.985) 13(0.2,-1.985) 14(0.6,-1.985) 15(1,-1.985) 26(1,1.985) 27(0.6,1.985) 28(0.2,1.985) 29(-0.2,1.985) 30(-0.6,1.985) 31(-1,1.985)
  Top Layer region: -1.897,1.301 -1.649,1.301 -1.649,1.333 -1.817,1.5 -1.897,1.5 -1.897,1.301
  Top Layer region: -1.918,-1.3 -1.648,-1.3 -1.648,-1.332 -1.816,-1.5 -1.918,-1.5 -1.918,-1.3
  Top Layer region: -1.301,-1.946 -1.301,-1.648 -1.333,-1.648 -1.501,-1.816 -1.501,-1.946 -1.301,-1.946
  Top Layer region: 1.3,-1.938 1.3,-1.646 1.332,-1.646 1.5,-1.814 1.5,-1.938 1.3,-1.938
  Top Layer region: 2.001,-1.299 1.65,-1.299 1.65,-1.331 1.818,-1.499 2.001,-1.499 2.001,-1.299
  Top Layer region: 1.976,1.301 1.649,1.301 1.649,1.333 1.817,1.501 1.976,1.501 1.976,1.301
  Top Layer region: 1.3,1.955 1.3,1.647 1.332,1.647 1.5,1.815 1.5,1.955 1.3,1.955
  Top Layer region: -1.3,1.96 -1.3,1.647 -1.332,1.647 -1.5,1.815 -1.5,1.96 -1.3,1.96
  Top Layer region: -1.4,1.05 -1.05,1.404 1.4,1.404 1.4,-1.4 -1.4,-1.4 -1.4,1.05
  silkscreen extent -2,1.8 -1.8,2, body extent -2,-2 2,2, height 0.55
QFN40_M040_5.0X5.0_EP_SL [mm] "QFN48_M050_SQ7.0_EP, SiLabs, High Density (C)"
  rrect5% 3.85x3.85 smd paste-1.95 mask+0.05: 0(0,0)
  rrect10% 0.74x0.22 smd mask+0.05: 1(-2.495,1.8) 2(-2.495,1.4) 3(-2.495,1) 4(-2.495,0.6) 5(-2.495,0.2) 6(-2.495,-0.2) 7(-2.495,-0.6) 8(-2.495,-1) 9(-2.495,-1.4) 10(-2.495,-1.8) 21(2.495,-1.8) 22(2.495,-1.4) 23(2.495,-1) 24(2.495,-0.6) 25(2.495,-0.2) 26(2.495,0.2) 27(2.495,0.6) 28(2.495,1) 29(2.495,1.4) 30(2.495,1.8)
  rrect10% 0.22x0.74 smd mask+0.05: 11(-1.8,-2.495) 12(-1.4,-2.495) 13(-1,-2.495) 14(-0.6,-2.495) 15(-0.2,-2.495) 16(0.2,-2.495) 17(0.6,-2.495) 18(1,-2.495) 19(1.4,-2.495) 20(1.8,-2.495) 31(1.8,2.495) 32(1.4,2.495) 33(1,2.495) 34(0.6,2.495) 35(0.2,2.495) 36(-0.2,2.495) 37(-0.6,2.495) 38(-1,2.495) 39(-1.4,2.495) 40(-1.8,2.495)
  body extent -2.5,-2.5 2.5,2.5, height 1.01
R0201_L#1 [mm] "Resistor, Chip; 0.60 mm L X 0.30 mm W X 0.28 mm H body"
  rrect52% 0.31x0.34 smd: 1(-0.275,0) 2(0.275,0)
  body extent -0.3,-0.15 0.3,0.15, height 0.23
R0201_L#2 [mm] "Resistor (Chip2PinSM127P600-8N) (170921)"
  rrect25% 0.34x0.32 smd: 1(-0.3,0) 2(0.3,0)
  body extent -0.32,-0.13 0.32,0.13, height 0.3
R0402_L [mm] "Chip Resistor, 2-Leads, Body 1.0x0.5mm, IPC High Density"
  rrect20% 0.6x0.6 smd mask+0.051: 1(-0.45,0) 2(0.45,0)
  body extent -0.5,-0.25 0.5,0.25, height 0.6
SKY13377-313LF [mm]
  rect 0.442x0.35 smd paste-0.05 mask+0.05: 1(-0.929,0.95) 2(-0.929,0) 3(-0.929,-0.95) 4(0.929,-0.95) 5(0.929,0) 6(0.929,0.95)
  round 0.1 smd paste-0.1 mask-0.1: 7(0,0)
  Top Layer region: -0.41,-0.61 -0.487,-0.595 -0.551,-0.551 -0.595,-0.487 -0.61,-0.41 -0.61,-0.41 -0.61,-0.175 -0.744,-0.175 -0.744,0.175 -0.61,0.175 -0.61,0.41 -0.51,0.437 -0.437,0.51 -0.41,0.61 -0.41,0.61 -0.102,0.61 -0.102,1.65 0.101,1.65 0.101,0.603 0.168,0.558 0.214,0.49 0.23,0.41 0.23,0.41 0.23,-0.41 0.215,-0.492 0.17,-0.562 0.101,-0.61 0.101,-0.61 0.101,-1.65 -0.102,-1.65 -0.102,-0.61
  body extent -1,-1.51 1.01,1.5
SOT-23-6_SN74LVC2G14 [mm]
  rect 1x0.7 smd paste-0.025: 1(-1.27,0.953) 2(-1.27,0) 3(-1.27,-0.953) 4(1.27,-0.953) 5(1.27,0) 6(1.27,0.953)
  body extent -1.21,-1.4 1.21,1.4, height 1.09
TP_1.0_SMD [mm] "Test Point, 1.0 mm, SMD"
  round 1 smd paste-0.501: 1(0,0)
  body extent -0.2,-0.2 0.2,0.2, height 0.01
X2DFN2_1.0x0.6_0.65P [mm] "ESD Diode"
  rrect20% 0.47x0.6 smd mask+0.051: 1(-0.365,0) 2(0.365,0)
  body extent -0.5,-0.25 0.5,0.25, height 0.6
X_MCS_CM8V-T1A [mm] "Crystal MCS CM8V-T1A (2 pin)"
  rrect25% 0.8x1.5 smd mask+0.051: 1(-0.75,0)
  rrect25% 0.85x1.5 smd mask+0.051: 2(0.75,0)
  body extent -1,-0.6 1,0.6, height 0.95

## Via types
v1: diameter 0.6, hole 0.25, IM4 GND to Bottom Layer, tented bottom, 3953 vias
v2: diameter 0.6, hole 0.25, Top Layer to Bottom Layer, tented both sides, 851 vias
v3: diameter 0.6, hole 0.25, IM4 GND to Bottom Layer, tented both sides, 179 vias

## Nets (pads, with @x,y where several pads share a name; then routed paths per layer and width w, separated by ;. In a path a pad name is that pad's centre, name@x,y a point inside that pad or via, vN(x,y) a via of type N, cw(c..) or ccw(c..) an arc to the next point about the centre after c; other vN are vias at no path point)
3V3: TPJ10.1
5V: TPJ12.1
50R_ANT_H1: ANT1.1 U205.25 | length 120
  Bottom Layer w0.2: -3.641,33.355 -2.41,34.6 U205.25@-1.985,34.6
  Bottom Layer w0.28: ANT1.1@-54,47 -54,61.55 -56.825,64.375 -65.275,64.375 -68.15,61.5 -68.15,46.475 -57.925,36.25 -35.6,36.25 -32.575,33.225 -16.15,33.225 -13.852,30.927 -6.983,30.927 -3.641,33.355
50R_ANT_H2: ANT2.1 U205.27 | length 120
  Bottom Layer w0.2: -4.537,35.036 -2.821,35.4 U205.27@-1.985,35.4
  Bottom Layer w0.28: ANT2.1@-18,47 -18,43.3 -20.425,40.875 -28.275,40.875 -35.925,48.525 -35.925,73.375 -34.2,75.1 -31.175,75.1 -29.375,73.3 -29.375,53.05 -26.7,50.375 -14.475,50.375 -11.6,47.5 -11.6,37.476 -8.521,34.397 -7.6,34.397 -7.004,34.521 -4.537,35.036
50R_ANT_H3: ANT3.1 U205.13 | length 120
  Bottom Layer w0.2: U205.13@1.985,35.8 2.767,35.8 4.57,36.008
  Bottom Layer w0.28: 4.57,36.008 6.1,37.538 6.1,59.35 11.55,64.8 37.975,64.8 39.1,63.675 39.1,61.3 37.975,60.175 22.475,60.175 20.625,58.325 20.625,55.175 19.45,54 17.675,54 16.375,55.3 16.375,58.3 14.9,59.775 12.175,59.775 10.625,58.225 10.625,49.4 13.025,47 ANT3.1@18,47
50R_ANT_H4: ANT4.1 U205.15 | length 120
  Bottom Layer w0.2: U205.15@1.985,35 2.588,35 4.111,34.17
  Bottom Layer w0.28: 4.111,34.17 8.61,32.166 16.691,32.166 20.7,36.175 42.925,36.175 45.8,39.05 57.325,39.05 58.45,40.175 58.45,41.925 57.325,43.05 52.05,43.05 47.738,47.362 47.738,53.087 43.25,57.575 43.25,63.175 44.95,64.875 50.35,64.875 52.125,63.1 52.125,48.875 ANT4.1@54,47
50R_ANT_H5: ANT5.1 U205.23 | length 120
  Bottom Layer w0.2: -2.25,32.103 -1.079,33.362 -1,33.447 U205.23@-1,34.015
  Bottom Layer w0.28: ANT5.1@-54,11 -59.3,16.3 -71.55,16.3 -74.675,13.175 -74.675,7.775 -71.325,4.425 -55,4.425 -42.375,17.05 -42.375,20.668 -36.218,26.825 -5.88,26.825 -4.501,28.205 -2.25,32.103
50R_ANT_H6: ANT6.1 U206.20 | length 120
  Bottom Layer w0.2: -4.475,-36.47 -2.784,-36.2 U206.20@-1.985,-36.2
  Bottom Layer w0.28: ANT6.1@-18,11 -22.3,11 -23.325,9.975 -23.325,8.2 -22.225,7.1 -18.925,7.1 -17.825,6 -17.825,4.3 -18.9,3.225 -26.7,3.225 -28.175,1.75 -28.175,-13.675 -30.975,-16.475 -34.35,-16.475 -36.025,-18.15 -36.025,-20.1 -34.775,-21.35 -33.125,-21.35 -31.7,-22.775 -31.7,-25.825 -36.9,-31.025 -41.1,-31.025 -42.575,-32.5 -42.575,-34.775 -41.525,-35.825 -12.45,-35.825 -11.439,-36.836 -7.956,-36.836 -4.475,-36.47
50R_ANT_H7: ANT7.1 U206.23 | length 120
  Bottom Layer w0.2: -3.897,-33.75 -2.552,-35 U206.23@-1.985,-35
  Bottom Layer w0.28: -3.897,-33.75 -6.928,-32 -8.875,-30.053 -8.875,-4.8 -2.875,1.2 -2.875,2.775 3.25,8.9 3.25,17.5 8.925,23.175 24.25,23.175 31.35,16.075 31.35,9.45 27.5,5.6 20.725,5.6 18,8.325 ANT7.1@18,11
50R_ANT_H8: ANT8.1 U205.17 | length 120
  Bottom Layer w0.2: U205.17@1.4,34.015 1.4,33.594 3.011,32.656
  Bottom Layer w0.28: 3.011,32.656 5.353,30.055 7.367,28.041 47.759,28.041 48.65,27.15 48.65,25.025 47.55,23.925 37.175,23.925 36.075,22.825 36.075,21.125 39.475,17.725 39.475,14.425 40.625,13.275 41.9,13.275 42.9,14.275 42.9,18.35 43.8,19.25 45.25,19.25 46.175,18.325 46.175,11.325 46.425,11.075 47.275,10.225 48.575,10.225 49.775,11.425 49.775,18.8 50.925,19.95 52.8,19.95 54,18.75 ANT8.1@54,11
50R_ANT_H9: ANT9.1 U205.21 | length 120
  Bottom Layer w0.2: -0.47,31.525 -0.2,33.215 U205.21@-0.2,34.015
  Bottom Layer w0.28: ANT9.1@-54,-25 -56.5,-27.5 -59.55,-27.5 -61.7,-25.35 -61.7,-22.225 -59.4,-19.925 -52.675,-19.925 -49.55,-23.05 -45.925,-23.05 -43.875,-21 -43.875,6.025 -27.35,22.55 -4.4,22.55 -0.836,26.114 -0.836,28.044 -0.47,31.525
50R_ANT_H10: ANT10.1 U206.21 | length 120
  Bottom Layer w0.2: -4.475,-35.53 -2.784,-35.8 U206.21@-1.985,-35.8
  Bottom Layer w0.28: ANT10.1@-18,-25 -20.2,-25 -21.175,-24.025 -21.175,-22.45 -20,-21.275 -16.775,-21.275 -14.4,-23.65 -14.4,-27.3 -16.275,-29.175 -22.025,-29.175 -24.65,-26.55 -24.65,-20.8 -21.275,-17.425 -21.275,-1 -22.325,0.05 -24.025,0.05 -25.025,-0.95 -25.025,-15.75 -28.4,-19.125 -28.4,-30.425 -26.5,-32.325 -12.575,-32.325 -9.736,-35.164 -7.956,-35.164 -4.475,-35.53
50R_ANT_H11: ANT11.1 U206.27 | length 120
  Bottom Layer w0.2: -0.936,-31.598 -0.622,-33.103 -0.6,-33.21 U206.27@-0.6,-34.015
  Bottom Layer w0.28: -0.936,-31.598 -1.362,-29.593 -1.362,-27.409 0.1,-25.948 0.1,-13.6 5.125,-8.575 7.275,-8.575 8.75,-10.05 8.75,-12.375 4.375,-16.75 4.375,-23.125 6.175,-24.925 11.325,-24.925 12.5,-23.75 12.5,-3.825 13.575,-2.75 15.775,-2.75 16.875,-3.85 16.875,-18.975 19.425,-21.525 26.225,-21.525 27.275,-22.575 27.275,-23.975 26.25,-25 ANT11.1@18,-25
50R_ANT_H12: ANT12.1 U206.26 | length 120
  Bottom Layer w0.2: -1.83,-31.889 -1,-33.379 U206.26@-1,-34.015
  Bottom Layer w0.28: -1.83,-31.889 -3.675,-27.747 -3.675,-12.525 8.95,0.1 32.825,0.1 39.75,-6.825 39.75,-27.075 41.75,-29.075 44.775,-29.075 47.075,-26.775 47.075,-21.725 49.2,-19.6 51.9,-19.6 54,-21.7 ANT12.1@54,-25
50R_ANT_H13: ANT13.1 U206.19 | length 120
  Bottom Layer w0.2: -4.28,-37.391 -2.647,-36.6 U206.19@-1.985,-36.6
  Bottom Layer w0.28: ANT13.1@-54,-61 -57.175,-64.175 -61.275,-64.175 -65.725,-59.725 -65.725,-46.575 -62.475,-43.325 -57.025,-43.325 -53.325,-47.025 -53.325,-54.45 -49.375,-58.4 -43.725,-58.4 -40.2,-54.875 -40.2,-41.075 -39.181,-40.056 -12.482,-40.056 -4.28,-37.391
50R_ANT_H14: ANT14.1 U206.17 | length 120
  Bottom Layer w0.2: -3.344,-39.011 -2.405,-37.4 U206.17@-1.985,-37.4
  Bottom Layer w0.28: ANT14.1@-18,-61 -14.15,-61 -12.25,-62.9 -12.25,-65.95 -14.275,-67.975 -41.6,-67.975 -43.6,-69.975 -43.6,-72.75 -41.625,-74.725 -11.125,-74.725 -7.8,-71.4 -7.8,-43.137 -6.662,-41.999 -3.344,-39.011
50R_ANT_H15: ANT15.1 U206.15 | length 120
  Bottom Layer w0.2: -1.83,-40.111 -1,-38.589 U206.15@-1,-37.985
  Bottom Layer w0.28: -1.83,-40.111 -3.161,-43.101 -3.161,-45.064 0.55,-48.775 18.2,-48.775 19.3,-49.875 19.3,-51.925 18.2,-53.025 5.35,-53.025 4.3,-54.075 4.3,-55.9 5.375,-56.975 21.3,-56.975 25.3,-60.975 25.3,-65.75 23.1,-67.95 6.25,-67.95 4.425,-66.125 4.425,-62.55 5.975,-61 ANT15.1@18,-61
50R_ANT_H16: ANT16.1 U206.14 | length 120
  Bottom Layer w0.2: -0.936,-40.402 -0.6,-38.694 U206.14@-0.6,-37.985
  Bottom Layer w0.28: -0.936,-40.402 -1.663,-43.825 -1.663,-44.487 -0.475,-45.675 23.225,-45.675 30.45,-52.9 48.02,-52.9 49.212,-54.091 49.212,-55.653 47.865,-57 42,-57 40.75,-58.25 40.75,-59.975 42.075,-61.3 48.5,-61.3 49.575,-62.375 49.575,-64.125 48.525,-65.175 41.025,-65.175 39.975,-66.225 39.975,-67.95 41.15,-69.125 52.825,-69.125 54,-67.95 ANT16.1@54,-61
50R_ANT_V1: ANT1.2 U205.26 | length 120
  Bottom Layer w0.2: -4.111,34.17 -2.622,35 U205.26@-1.985,35
  Bottom Layer w0.28: ANT1.2@-47,54 -47,69.175 -50.275,72.45 -56.5,72.45 -57.8,73.75 -57.8,75.625 -56.5,76.925 -44.825,76.925 -41.125,73.225 -41.125,47.475 -29.725,36.075 -14.829,36.075 -11.5,32.746 -7.308,32.746 -4.111,34.17
50R_ANT_V2: ANT2.2 U205.28 | length 120
  Bottom Layer w0.2: -4.535,36.004 -2.916,35.8 U205.28@-1.985,35.8
  Bottom Layer w0.28: ANT2.2@-11,54 -22.775,54 -24.7,55.925 -24.7,59.05 -22.575,61.175 -12.225,61.175 -10.45,62.95 -10.45,66.2 -12.375,68.125 -22,68.125 -24.325,70.45 -24.325,74.45 -22.275,76.5 -8.475,76.5 -5.675,73.7 -5.675,42.175 -7.6,40.25 -7.6,37.867 -5.911,36.178 -4.535,36.004
50R_ANT_V3: ANT3.2 U205.14 | length 120
  Bottom Layer w0.2: U205.14@1.985,35.4 2.693,35.4 4.402,35.064
  Bottom Layer w0.28: 4.402,35.064 9.807,33.916 11.541,33.916 13.425,35.8 13.425,37.725 12.25,38.9 10.35,38.9 9.225,40.025 9.225,41.7 10.3,42.775 19.975,42.775 22.05,44.85 22.05,47.925 23.2,49.075 24.975,49.075 26.075,47.975 26.075,41.8 28.15,39.725 30.3,39.725 32.35,41.775 43.475,41.775 44.85,43.15 44.85,45.025 43.515,46.36 30.95,46.36 29.625,47.685 29.625,49.475 30.75,50.6 38.075,50.6 39.525,52.05 39.525,54.5 37.9,56.125 27.125,56.125 ANT3.2@25,54
50R_ANT_V4: ANT4.2 U205.16 | length 120
  Bottom Layer w0.2: U205.16@1.985,34.6 2.405,34.6 3.641,33.355
  Bottom Layer w0.28: 3.641,33.355 7.858,30.291 20.65,30.291 22.434,32.075 44.375,32.075 48.3,36 50.675,36 51.925,34.75 51.925,32.175 53.35,30.75 60.025,30.75 61.95,32.675 61.95,46.525 56.325,52.15 56.325,63.475 58.025,65.175 61.325,65.175 63.175,63.325 63.175,56.175 ANT4.2@61,54
50R_ANT_V5: ANT5.2 U205.24 | length 120
  Bottom Layer w0.2: -3.011,32.656 -1.4,33.598 U205.24@-1.4,34.015
  Bottom Layer w0.28: ANT5.2@-47,18 -47,21.55 -50.125,24.675 -72.05,24.675 -75.075,27.7 -75.075,33.4 -72.357,36.118 -67.068,36.118 -60.9,29.95 -16.825,29.95 -15.75,28.875 -6.508,28.875 -5.578,29.805 -3.011,32.656
50R_ANT_V6: ANT6.2 U205.20 | length 120
  Bottom Layer w0.2: U205.20@0.2,34.015 0.2,33.215 0.47,31.525
  Bottom Layer w0.28: ANT6.2@-11,18 -23.525,18 -35.75,5.775 -35.75,-7.375 -36.925,-8.55 -38.65,-8.55 -39.85,-7.35 -39.85,5.975 -25.475,20.35 -2.1,20.35 0.836,23.286 0.836,28.044 0.47,31.525
50R_ANT_V7: ANT7.2 U206.24 | length 120
  Bottom Layer w0.2: -3.344,-32.989 -2.401,-34.6 U206.24@-1.985,-34.6
  Bottom Layer w0.28: -3.344,-32.989 -5.945,-30.647 -7.125,-29.467 -7.125,-7.775 0.35,-0.3 0.35,1.425 5.35,6.425 12.05,6.425 13.625,8 13.625,10.275 12.075,11.825 8.675,11.825 6.925,13.575 6.925,16.7 10.825,20.6 21.225,20.6 22.075,19.75 22.075,18.575 21.275,17.775 13.3,17.775 12.45,16.925 12.45,15.675 13.4,14.725 19,14.725 21.7,12.025 23.65,12.025 25,13.375 ANT7.2@25,18
50R_ANT_V8: ANT8.2 U205.18 | length 120
  Bottom Layer w0.2: U205.18@1,34.015 1,33.451 2.25,32.103
  Bottom Layer w0.28: 2.25,32.103 3.876,29.287 4,29.072 7.419,25.653 26.447,25.653 35.6,16.5 35.6,11.95 47.225,0.325 51.6,0.325 56.8,5.525 59.95,5.525 62.475,8.05 62.475,11.475 57,16.95 57,20.375 53.625,23.75 53.625,25.9 55.225,27.5 58.95,27.5 61,25.45 ANT8.2@61,18
50R_ANT_V9: ANT9.2 U205.22 | length 120
  Bottom Layer w0.2: -1.391,31.72 -0.6,33.329 U205.22@-0.6,34.015
  Bottom Layer w0.28: ANT9.2@-47,-18 -50.75,-14.25 -66.7,-14.25 -68.725,-12.225 -68.725,-8.475 -66.875,-6.625 -53.599,-6.625 -49.975,-3.001 -49.975,4.375 -29.7,24.65 -5.543,24.65 -2.795,27.399 -1.391,31.72
50R_ANT_V10: ANT10.2 U206.22 | length 120
  Bottom Layer w0.2: -4.28,-34.609 -2.914,-35.281 -2.67,-35.4 U206.22@-1.985,-35.4
  Bottom Layer w0.28: ANT10.2@-11,-18 -14.95,-14.05 -14.95,-3.325 -11.6,0.025 -7.85,0.025 -6.775,1.1 -6.775,2.475 -7.8,3.5 -10.05,3.5 -11.425,4.875 -11.425,7.125 -10.05,8.5 -1.4,8.5 -0.375,9.525 -0.375,10.9 -1.35,11.875 -12.475,11.875 -14.825,9.525 -14.825,0.975 -18.625,-2.825 -18.625,-15.1 -11.575,-22.15 -11.575,-29.561 -7.608,-33.528 -4.28,-34.609
50R_ANT_V11: ANT11.2 U206.28 | length 120
  Bottom Layer w0.2: U206.28@-0.2,-34.015 -0.2,-33.085 0,-31.5
  Bottom Layer w0.28: 0,-31.5 0,-30.525 1.875,-28.65 32.725,-28.65 35.8,-25.575 35.8,-8.175 31.2,-3.575 22.55,-3.575 21.1,-5.025 21.1,-7.15 22.725,-8.775 30.525,-8.775 32.25,-10.5 32.25,-18.275 31.15,-19.375 29.475,-19.375 28.3,-18.2 28.3,-13.525 26.875,-12.1 24.25,-12.1 22.825,-13.525 22.825,-15.825 ANT11.2@25,-18
50R_ANT_V12: ANT12.2 U206.25 | length 120
  Bottom Layer w0.2: -2.645,-32.359 -1.4,-33.59 U206.25@-1.4,-34.015
  Bottom Layer w0.28: -2.645,-32.359 -5.4,-28.568 -5.4,-9.875 7.625,3.15 38.875,3.15 49.325,-7.3 49.325,-9.75 47.575,-11.5 44.975,-11.5 43.625,-12.85 43.625,-14.65 45.075,-16.1 53.75,-16.1 55.65,-18 ANT12.2@61,-18
50R_ANT_V13: ANT13.2 U205.19 | length 120
  Bottom Layer w0.2: U205.19@0.6,34.015 0.6,33.352 1.391,31.72
  Bottom Layer w0.28: ANT13.2@-47,-54 -47,-30.8 -39.425,-23.225 -39.425,-17.1 -31.925,-9.6 -31.925,4.95 -22.275,14.6 -3.525,14.6 2.75,20.875 2.75,27.536 1.391,31.72
50R_ANT_V14: ANT14.2 U206.18 | length 120
  Bottom Layer w0.2: -3.897,-38.25 -2.548,-37 U206.18@-1.985,-37
  Bottom Layer w0.28: ANT14.2@-11,-54 -14.075,-57.075 -19.7,-57.075 -23.675,-61.05 -34.275,-61.05 -36.1,-59.225 -36.1,-54.225 -33.775,-51.9 -15.175,-51.9 -14.15,-50.875 -14.15,-48.925 -15.2,-47.875 -34.65,-47.875 -35.7,-46.825 -35.7,-44.9 -34.725,-43.925 -11.414,-43.925 -8.258,-40.768 -3.897,-38.25
50R_ANT_V15: ANT15.2 U206.16 | length 120
  Bottom Layer w0.2: -2.645,-39.641 -1.4,-38.405 U206.16@-1.4,-37.985
  Bottom Layer w0.28: -2.645,-39.641 -4.937,-42.796 -4.937,-47.5 0.1,-52.537 0.1,-65.3 -3.85,-69.25 -3.85,-73.65 -1.2,-76.3 2.65,-76.3 5.725,-73.225 9.85,-73.225 12.9,-76.275 30.825,-76.275 35.975,-71.125 35.975,-68.425 34.125,-66.575 31.75,-66.575 30.425,-65.25 30.425,-63.325 31.7,-62.05 34.575,-62.05 36.1,-60.525 36.1,-57.775 34.65,-56.325 27.275,-56.325 ANT15.2@25.025,-54.075 ; ANT15.2@25,-54 ANT15.2@25.05,-54.05
50R_ANT_V16: ANT16.2 U206.13 | length 120
  Bottom Layer w0.2: U206.13@-0.2,-37.985 -0.2,-38.767 0,-40.5
  Bottom Layer w0.28: 0,-40.5 0,-41.95 0.75,-42.7 54.15,-42.7 55,-43.55 55,-45.1 54.25,-45.85 31.7,-45.85 30.9,-46.65 30.9,-48.225 31.75,-49.075 56.075,-49.075 ANT16.2@61,-54
50R_C1: C1.1 L1.1 U1.14 | length 2
  Bottom Layer w0.2: L1.1@65.95,-35.55 L1.1@65.975,-35.55 C1.1@66.475,-35.55 ; C1.1@66.475,-35.55 C1.1@66.5,-35.55 ; U1.14@67.255,-35.55 U1.14@67.238,-35.55 ; C1.1@66.5,-35.55 U1.14@67.238,-35.55 ; C1.1@66.5,-35.55 U1.14@67.238,-35.55
50R_CC1: C2.1 CC1.1 L1.2 | length 1.1
  Bottom Layer w0.2: CC1.1@64.3,-35.55 L1.2@65.375,-35.55
50R_HYBRID_IN: H1.1 R208.2 | length 33.2
  Top Layer w0.28: v2(71.443,37.9) 71.443,64.843 v2(71.45,64.85)
  Bottom Layer w0.28: H1.1@67.655,63.746 67.655,64.755 68.225,65.325 70.975,65.325 v2(71.45,64.85) ; R208.2@70.467,37.889 70.479,37.9 v2(71.443,37.9)
50R_HYBRID_OUT_I: CC42.2 R210.2 R211.2 | length 45
  Bottom Layer w0.28: CC42.2@63.638,1.64 65.29,1.64 66.55,2.9 66.55,18.575 64.55,20.575 64.55,40.45 65.55,41.45 R210.2@67.32,41.45
50R_HYBRID_OUT_Q: CC32.2 R212.2 R213.2 | length 41.9
  Top Layer w0.28: v2(74.525,41.45) v2(74.525,70.1)
  Bottom Layer w0.28: CC32.2@66.106,76.507 68.118,76.507 69.769,74.856 69.769,72.856 72.525,70.1 v2(74.525,70.1) ; R212.2@73.52,41.45 v2(74.525,41.45)
50R_LYNX_OUT: D13.2 R1.2 U201.5 | length 43.2
  Bottom Layer w0.28: R1.2@72.195,-18.597 72.195,-15.13 76.541,-10.784 76.541,-0.466 71.7,4.375 71.7,14.075 73.5,15.875 U201.5@73.5,20.071
50R_P2: P202.1 R2.2 | length 1.7
  Bottom Layer w0.28: R2.2@73.095,-19.497 P202.1@74.795,-19.497
50R_R1: C3.1 CC1.2 R1.1 R2.1 | length 25.5
  Bottom Layer w0.28: C3.1@63.125,-35.45 61.796,-34.121 60.675,-34.121 59.927,-33.373 59.927,-28.523 66.125,-22.325 69.367,-22.325 R2.1@72.195,-19.497 ; C3.1@63.2,-35.55 CC1.2@63.75,-35.55
50R_U101_OUT1: CC11.1 D23.2 U202.5 | length 7.1
  Bottom Layer w0.28: D23.2@73.5,29.455 U202.5@73.5,31.071 ; D23.2@73.524,29.455 73.524,27.268 CC11.1@75.838,24.954
50R_U101_OUT2: CC12.1 R208.1 R209.2 | length 14.1
  Top Layer w0.28: v2(69.567,36.991) 71.813,34.745 v2(71.813,29.206)
  Bottom Layer w0.28: v2(69.567,36.991) R208.1@69.567,37.889 ; CC12.1@71.212,24.974 71.813,25.575 v2(71.813,29.206)
50R_U102_OUT1: CC31.2 D21.2 U202.3 | length 47
  Bottom Layer w0.28: CC31.2@65.92,72.692 71.087,67.525 74.3,67.525 76.65,65.175 76.65,35.129 U202.3@74.45,32.929
50R_U102_OUT2: CC41.2 D22.2 U202.1 | length 47
  Bottom Layer w0.28: CC41.2@66.204,-1.189 68.611,-1.189 70.225,0.425 70.225,2.775 69.1,3.9 69.1,20.125 67.05,22.175 67.05,34.375 68.225,35.55 69.93,35.55 U202.1@72.533,32.947
50R_U103_OUT: C11.2 CC33.1 L11.1 R215.1 | length 85.5
  Bottom Layer w0.28: L11.1@-0.075,39.625 -0.075,62.15 10.557,72.782 55.608,72.782 CC33.1@57.651,74.825
50R_U104_OUT: C21.2 CC43.1 L21.1 R217.1 | length 85.5
  Bottom Layer w0.28: R217.1@3.497,-35.931 48.269,-35.931 64.275,-19.925 64.275,-16.8 57.1,-9.625 57.1,-7.278 CC43.1@58.85,-5.528
BOARD_ID_SCL: TPJ14.1
BOARD_ID_SDA: TPJ15.1
BOARD_ID_WP: TPJ16.1
CP/DP+: U201.6 U203.6 U204.6 U208.4 | length 122.8
  IM3 Signal w0.2: v2(60.178,75.775) 68.975,75.775 72.85,71.9 72.85,68.226 74.551,66.525 74.551,44.474 76.125,42.9 76.125,40 74.53,38.405 74.53,20.884 75.624,19.79 75.624,18.92 v2(75.075,18.371) 74.7,17.996 74.7,11.25 75.425,10.525 ; v2(74.775,-1.45) 74.977,-1.45 74.775,-1.248 74.775,6.25 75.425,6.9 75.425,10.525 ; v2(76.895,8.64) 76.895,9.93 76.3,10.525 75.425,10.525
  IM2 Signal w0.2: v2(58.375,0.45) 70.6,0.45 72.5,-1.45 v2(74.775,-1.45) ; v2(71.395,19.739) 72.763,18.371 v2(75.075,18.371)
  Bottom Layer w0.2: v2(58.375,0.45) 58.375,-0.911 59.987,-2.523 U204.6@60.511,-2.523 ; v2(60.178,75.775) U203.6@60.951,75.775 ; v2(71.395,19.739) 71.726,20.071 U201.6@72.55,20.071 ; U208.4@76.895,7.878 v2(76.895,8.64)
CP/DP-: U201.4 U203.4 U204.4 U208.3 U208.6 | length 111
  IM3 Signal w0.2: v2(60.951,73.392) 70.683,73.392 72.45,71.625 72.45,67.876 74.251,66.075 74.251,44.149 75.725,42.675 75.725,40.25 74.23,38.755 74.23,20.291 v2(75.066,19.455) 74.275,18.665 74.275,9.044 v2(74.655,8.664) 74.655,7.192 74.25,6.787 74.25,-3.35 74.5,-3.6 v2(74.5,-4.8)
  Bottom Layer w0.2: U204.4@61.855,-3.866 62.788,-4.8 v2(74.5,-4.8) ; U201.4@74.45,20.071 v2(75.066,19.455) ; v2(74.655,8.664) 74.655,8.177 U208.3@74.355,7.878 75.06,7.878 75.496,7.441 75.496,6.41 75.933,5.973 U208.6@76.895,5.973
  Bottom Layer w0.35: v2(60.951,73.392) U203.4@60.951,73.875
CTRL1: J201.7 U1.1 U205.7 U206.7 | length 355.9
  IM3 Signal w0.1: J201.7@52.15,-76.45 54.45,-74.15 70.6,-74.15 76.6,-68.15 76.6,-59.45 75.25,-58.1 75.25,-54.15 74.854,-53.754 74.854,-49.871 v2@75.175,-49.55 ; v2(58.25,71.5) 59.025,72.275 60.2,72.275 60.95,71.525 70.925,71.525 71.6,70.85 71.6,67.325 73.568,65.357 73.568,44.518 72.475,43.425 72.475,39.525 73.568,38.432 73.568,-14.29 72.825,-15.033 72.825,-32.075 72.35,-32.55 72.35,-35.875 72.198,-36.027 72.198,-37.804 74.425,-40.03 v2(74.425,-42.65) ; v2(72.325,-47.9) 72.325,-46.725 74.45,-44.6 74.45,-42.922 v2@74.475,-42.897
  Bottom Layer w0.1: U1.1@71.55,-37.445 71.55,-38.625 74.425,-41.5 v2(74.425,-42.65)
  Bottom Layer w0.2: U205.7@1,37.985 1,38.45 2.5,39.95 2.5,60.138 11.012,68.65 57.275,68.65 58.25,69.625 v2(58.25,71.5) ; U206.7@1.985,-37 2.499,-37 3.524,-38.025 38.039,-38.025 38.929,-38.915 58.323,-38.915 60.303,-40.894 60.303,-45.228 62.65,-47.575 72,-47.575 v2(72.325,-47.9) 72.775,-47.9 74.4,-49.525 v2(75.2,-49.525)
CTRL2: J201.8 U1.2 U205.8 U206.8 | length 354
  IM3 Signal w0.1: J201.8@54.692,-76.45 56.665,-74.475 70.617,-74.475 76.9,-68.192 76.9,-59.3 76.225,-58.625 76.225,-51 v2@75.5,-50.275 ; v2(58.925,71.075) 58.95,71.1 58.95,71.75 59.25,72.05 60.025,72.05 60.75,71.325 70.625,71.325 71.35,70.6 71.35,67.225 73.368,65.207 73.368,44.725 72.25,43.607 72.25,39.4 73.368,38.282 73.368,-14.207 72.6,-14.975 72.6,-31.825 72.15,-32.275 72.15,-35.75 71.998,-35.902 71.998,-37.887 73.775,-39.663 73.775,-43.441 v2(73.782,-43.448) 73.798,-43.448 74.25,-43.9 74.25,-44.45 71.75,-46.95 v2(71.75,-48.45)
  Bottom Layer w0.1: U1.2@71.15,-37.445 71.15,-38.6 73.775,-41.225 v2@73.775,-43.45
  Bottom Layer w0.2: U205.8@1.4,37.985 1.4,38.4 2.8,39.8 2.8,60.014 11.111,68.325 57.525,68.325 58.925,69.725 v2(58.925,71.075) ; U206.8@1.985,-37.4 2.475,-37.4 3.399,-38.325 36.117,-38.325 37.915,-38.325 38.805,-39.215 58.199,-39.215 60.003,-41.018 60.003,-45.453 62.55,-48 71.3,-48 v2(71.75,-48.45) 72.55,-48.45 74.375,-50.275 v2(75.525,-50.275)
